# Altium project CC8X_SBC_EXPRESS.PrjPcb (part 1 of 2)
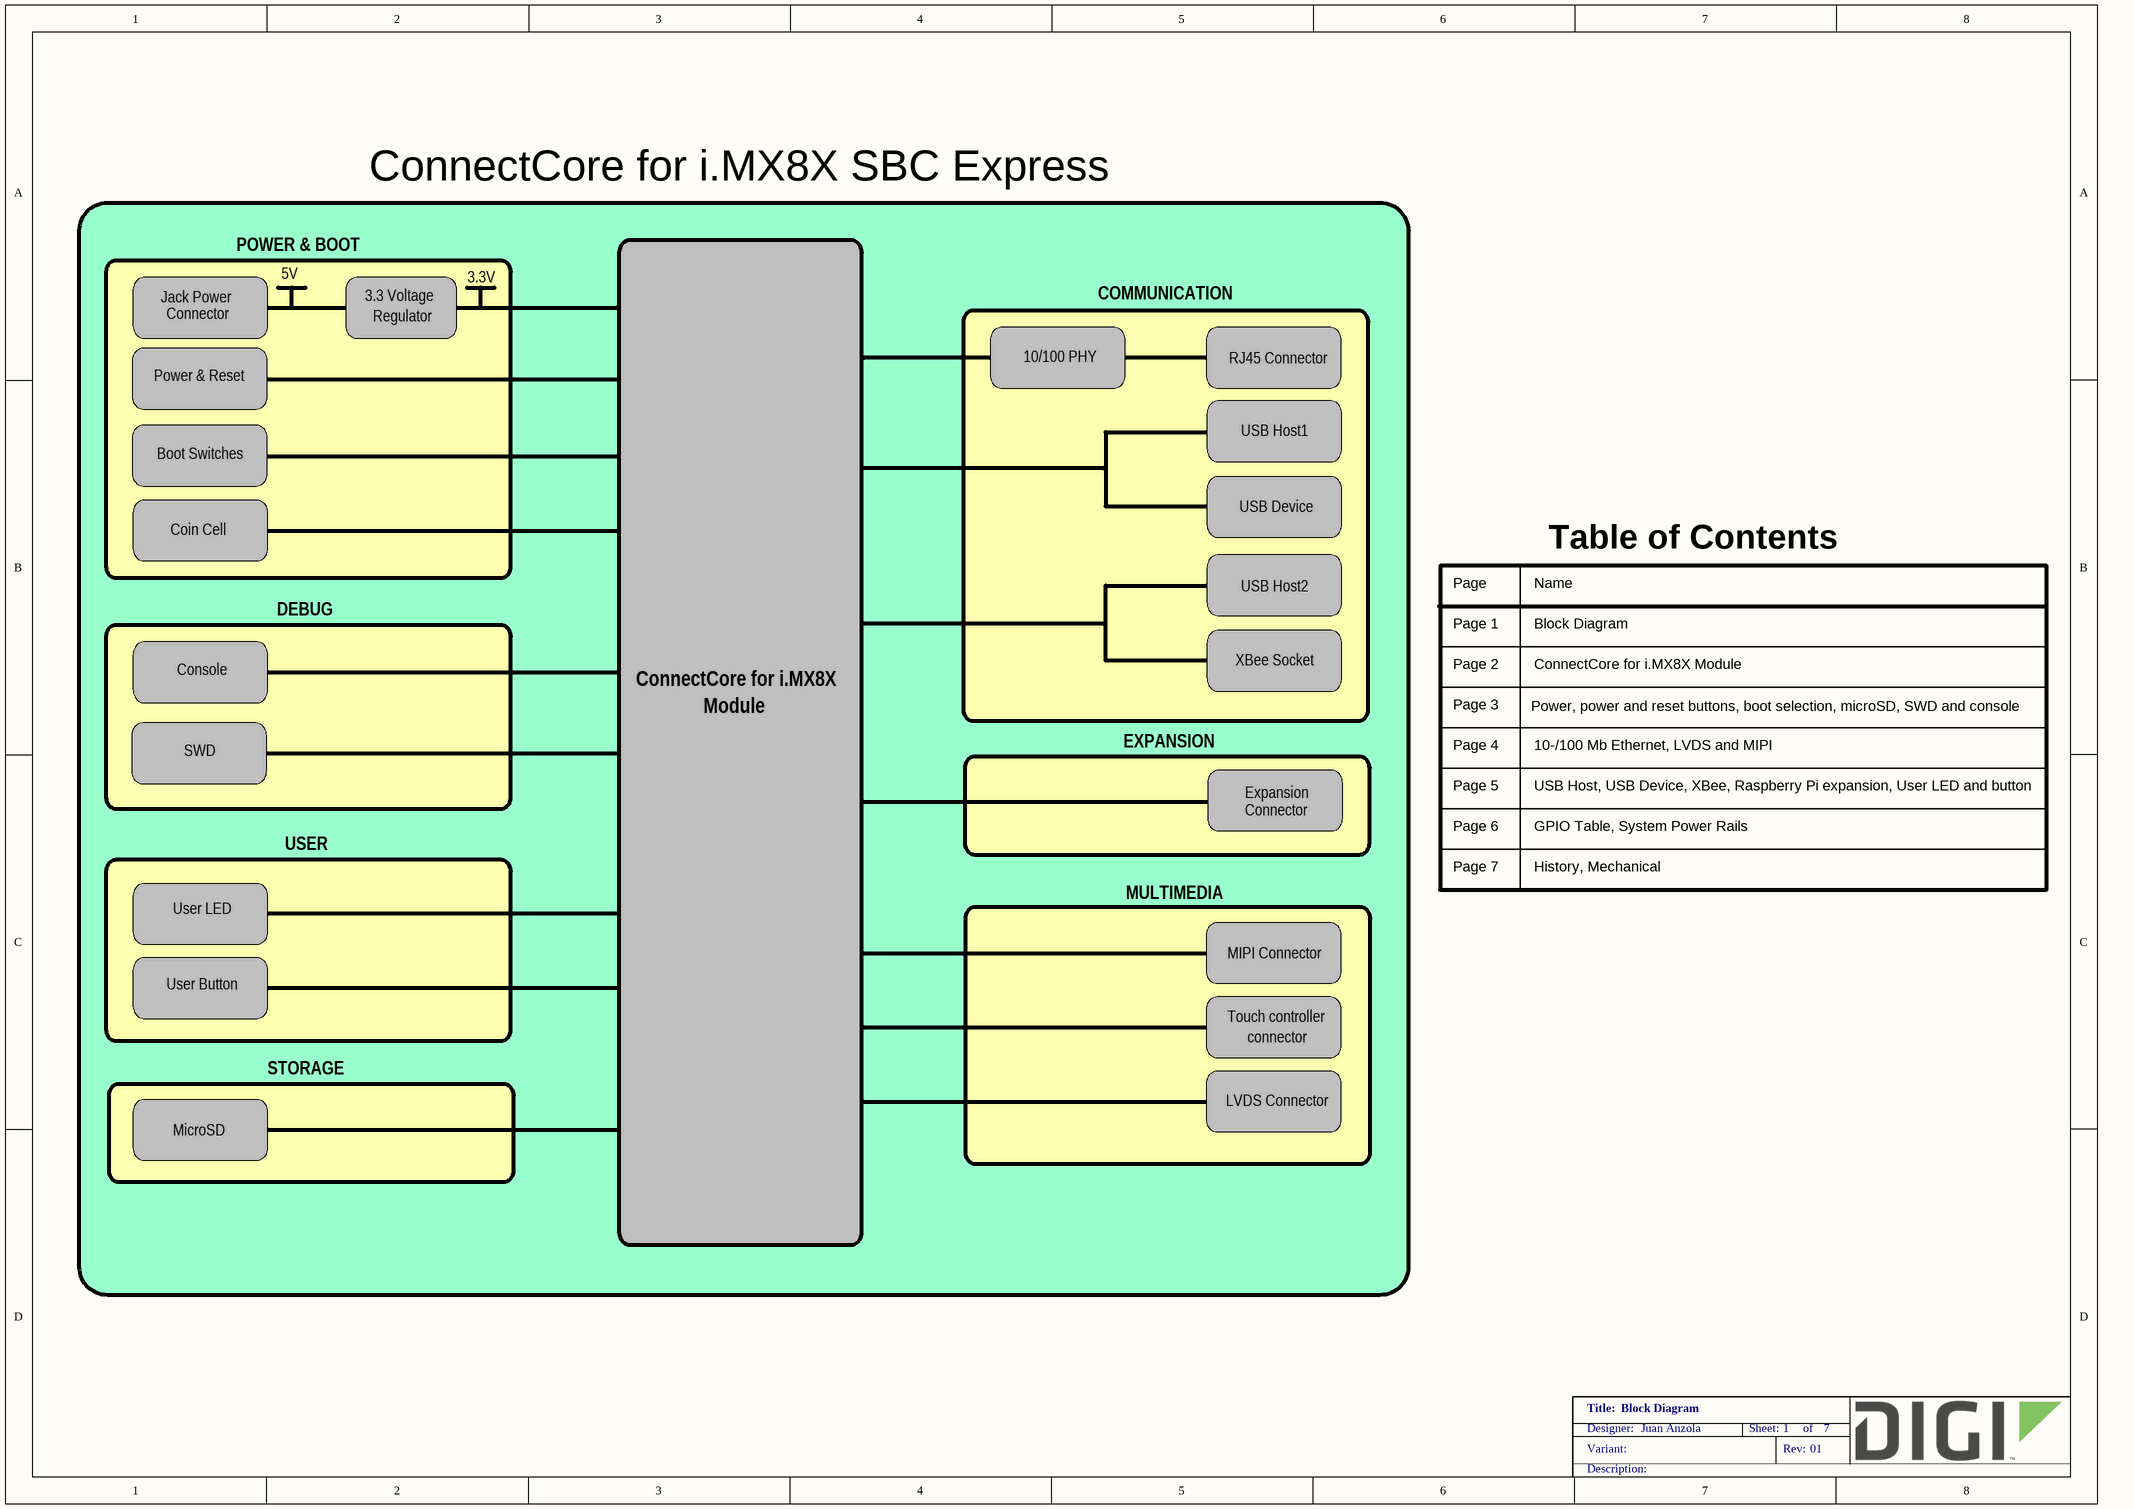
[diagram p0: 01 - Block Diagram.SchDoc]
VariantRevision: 01
7 sheets, 169 parts. Net scope: flat (ports and power ports of the same name join across sheets).
Board file: 30015582_02_A_CC8X_SBC_EXPRESS.PcbDoc
Sheets:
  01 - Block Diagram.SchDoc
  02 - CC8X Module.SchDoc
  03 - Power, boot mode, reset, console, microSD, SWD, Coin Cell.SchDoc
  04 - 10-100 Mb Ethernet, LVDS, MIPI.SchDoc
  05 - USB Host-Device, Raspberry PI expansion, User LED and button, XBee.SchDoc
  06 - GPIO Table, System Power rails.SchDoc
  07 - History, Mechanicals.SchDoc

## Sheet 01 - Block Diagram.SchDoc: Block Diagram
size A3; PageSetup: Record=PageOptions¦CenterHorizontal=True¦CenterVertical=True¦PrintScale=0.70¦XCorrection=1.00¦YCorrection=1.00¦PrintKind=0¦BorderSize=5000000¦LeftOffset=0¦BottomOffset=0¦Orientation=2¦PaperLength=4200¦PaperWidth=2970¦Scale=100¦PaperSource=7¦PrintQuality=600¦MediaType=1¦DitherType=10¦PaperKind=A4¦PrintScaleMode=1; Author: Juan Anzola; SheetNumber: 1; SheetTotal: 7

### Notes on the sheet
- ConnectCore for i.MX8X SBC Express
- Jack Power
- POWER & BOOT
- 5V
- 3.3 Voltage
- 3.3V
- COMMUNICATION
- Power & Reset
- Connector
- Regulator
- 10/100 PHY
- RJ45 Connector
- USB Host1
- Boot Switches
- USB Device
- Coin Cell
- Page
- Name
- Table of Contents
- DEBUG
- USB Host2
- Page 1
- Block Diagram
- Console
- ConnectCore for i.MX8X
- Module
- XBee Socket
- Page 2
- Page 3
- Power, power and reset buttons, boot selection, microSD, SWD and console
- ConnectCore for i.MX8X Module
- SWD
- EXPANSION
- Page 4
- 10-/100 Mb Ethernet, LVDS and MIPI
- USER
- Expansion
- Page 5
- Page 6
- USB Host, USB Device, XBee, Raspberry Pi expansion, User LED and button
- GPIO Table, System Power Rails
- User LED
- MULTIMEDIA
- Page 7
- History, Mechanical
- User Button
- MIPI Connector
- Touch controller
- connector
- STORAGE
- LVDS Connector
- MicroSD

## Sheet 02 - CC8X Module.SchDoc: ConnectCore for i.MX6UL module
size A2; PageSetup: Record=PageOptions¦CenterHorizontal=True¦CenterVertical=True¦PrintScale=0.71¦XCorrection=1.00¦YCorrection=1.00¦PrintKind=0¦BorderSize=5000000¦LeftOffset=0¦BottomOffset=0¦Orientation=2¦PaperLength=4200¦PaperWidth=2970¦Scale=100¦PaperSource=257¦PrintQuality=600¦MediaType=1¦DitherType=10¦PaperKind=A3¦PrintScaleMode=1; Author: Juan Anzola; Organization: Altium Limited; Address1: L3, 12a Rodborough Rd; Address2: Frenchs Forest; Address3: NSW; Address4: Australia 2086; SheetNumber: 2; SheetTotal: 7
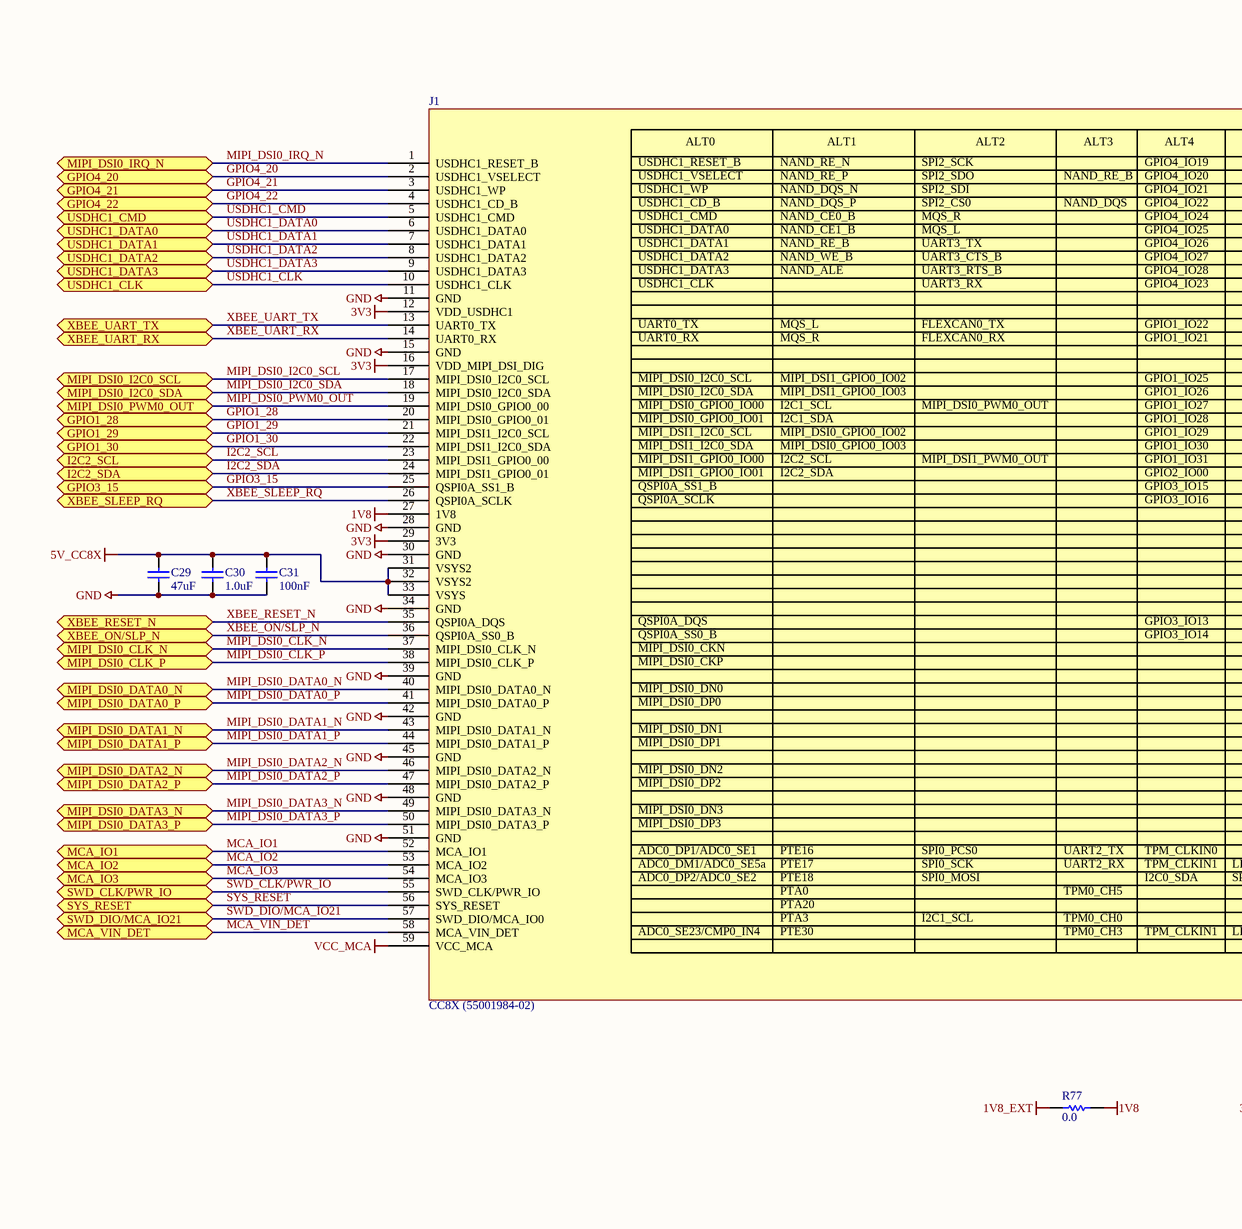
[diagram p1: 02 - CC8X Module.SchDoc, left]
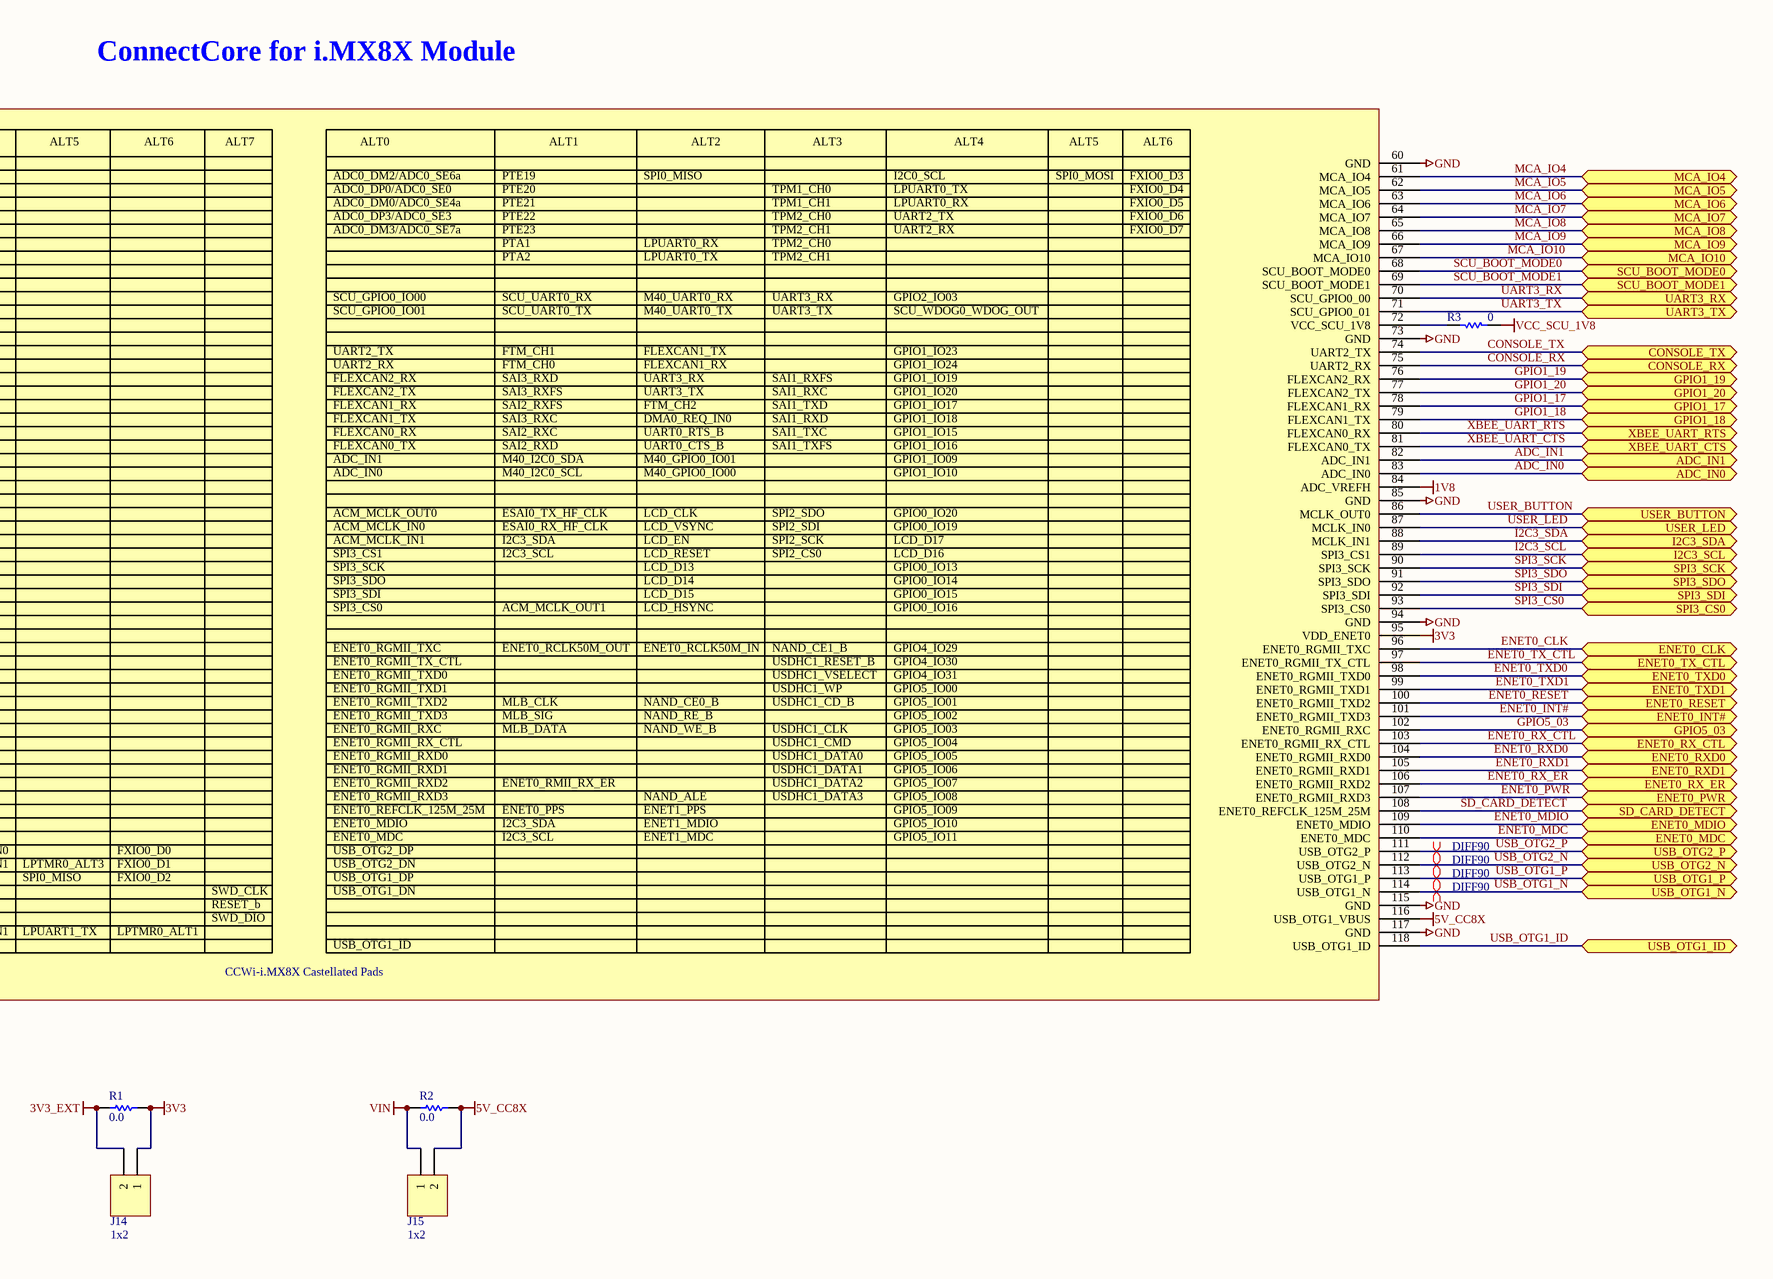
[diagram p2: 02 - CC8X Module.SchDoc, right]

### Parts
C29  47uF  [CAPC2013X145N]
C30  1.0uF  [CAPC1005X55L]
C31  100nF  [CAPC1005X55N]
J1  CC8X (55001984-02)  [CC8X_CASTELLATED]
J14  1x2  [FCI_68002-102HLF]
J15  1x2  [FCI_68002-102HLF]
R1  0.0  [RESC2013X70N]
R2  0.0  [RESC2013X70N]
R3  0  [RESC1005X40N]
R77  0.0  [RESC2013X70N]

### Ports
ADC_IN0 (bidir), ADC_IN1 (bidir), CONSOLE_RX (bidir), CONSOLE_TX (bidir), ENET0_CLK (bidir), ENET0_INT# (bidir), ENET0_MDC (bidir), ENET0_MDIO (bidir), ENET0_PWR (bidir), ENET0_RESET (bidir), ENET0_RX_CTL (bidir), ENET0_RX_ER (bidir), ENET0_RXD0 (bidir), ENET0_RXD1 (bidir), ENET0_TX_CTL (bidir), ENET0_TXD0 (bidir), ENET0_TXD1 (bidir), GPIO1_17 (bidir), GPIO1_18 (bidir), GPIO1_19 (bidir), GPIO1_20 (bidir), GPIO1_28 (bidir), GPIO1_29 (bidir), GPIO1_30 (bidir), GPIO3_15 (bidir), GPIO4_20 (bidir), GPIO4_21 (bidir), GPIO4_22 (bidir), GPIO5_03 (bidir), I2C2_SCL (bidir), I2C2_SDA (bidir), I2C3_SCL (bidir), I2C3_SDA (bidir), MCA_IO1 (bidir), MCA_IO2 (bidir), MCA_IO3 (bidir), MCA_IO4 (bidir), MCA_IO5 (bidir), MCA_IO6 (bidir), MCA_IO7 (bidir), MCA_IO8 (bidir), MCA_IO9 (bidir), MCA_IO10 (bidir), MCA_VIN_DET (bidir), MIPI_DSI0_CLK_N (bidir), MIPI_DSI0_CLK_P (bidir), MIPI_DSI0_DATA0_N (bidir), MIPI_DSI0_DATA0_P (bidir), MIPI_DSI0_DATA1_N (bidir), MIPI_DSI0_DATA1_P (bidir), MIPI_DSI0_DATA2_N (bidir), MIPI_DSI0_DATA2_P (bidir), MIPI_DSI0_DATA3_N (bidir), MIPI_DSI0_DATA3_P (bidir), MIPI_DSI0_I2C0_SCL (bidir), MIPI_DSI0_I2C0_SDA (bidir), MIPI_DSI0_IRQ_N (bidir), MIPI_DSI0_PWM0_OUT (bidir), SCU_BOOT_MODE0 (bidir), SCU_BOOT_MODE1 (bidir), SD_CARD_DETECT (bidir), SPI3_CS0 (bidir), SPI3_SCK (bidir), SPI3_SDI (bidir), SPI3_SDO (bidir), SWD_CLK/PWR_IO (bidir), SWD_DIO/MCA_IO21 (bidir), SYS_RESET (bidir), UART3_RX (bidir), UART3_TX (bidir), USB_OTG1_ID (bidir), USB_OTG1_N (bidir), USB_OTG1_P (bidir), USB_OTG2_N (bidir), USB_OTG2_P (bidir), USDHC1_CLK (bidir), USDHC1_CMD (bidir), USDHC1_DATA0 (bidir), USDHC1_DATA1 (bidir), USDHC1_DATA2 (bidir), USDHC1_DATA3 (bidir), USER_BUTTON (bidir), USER_LED (bidir), XBEE_ON/SLP_N (bidir), XBEE_RESET_N (bidir), XBEE_SLEEP_RQ (bidir), XBEE_UART_CTS (bidir), XBEE_UART_RTS (bidir), XBEE_UART_RX (bidir), XBEE_UART_TX (bidir)

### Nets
1V8: J1.27(1V8) J1.84(ADC_VREFH) R77.2
1V8_EXT: R77.1
3V3: J1.12(VDD_USDHC1) J1.16(VDD_MIPI_DSI_DIG) J1.29(3V3) J1.95(VDD_ENET0) J14.1 R1.2
3V3_EXT: J14.2 R1.1
5V_CC8X: C29.2 C30.2 C31.1 J1.31(VSYS2) J1.32(VSYS2) J1.33(VSYS) J1.116(USB_OTG1_VBUS) J15.2 R2.2
GND: C29.1 C30.1 C31.2 J1.11(GND) J1.15(GND) J1.28(GND) J1.30(GND) J1.34(GND) J1.39(GND) J1.42(GND) J1.45(GND) J1.48(GND) J1.51(GND) J1.60(GND) J1.73(GND) J1.85(GND) J1.94(GND) J1.115(GND) J1.117(GND)
VCC_MCA: J1.59(VCC_MCA)
VCC_SCU_1V8: R3.2
VIN: J15.1 R2.1
ADC_IN0: J1.83(ADC_IN0) ; port ADC_IN0
ADC_IN1: J1.82(ADC_IN1) ; port ADC_IN1
CONSOLE_RX: J1.75(UART2_RX) ; port CONSOLE_RX
CONSOLE_TX: J1.74(UART2_TX) ; port CONSOLE_TX
ENET0_CLK: J1.96(ENET0_RGMII_TXC) ; port ENET0_CLK
ENET0_INT#: J1.101(ENET0_RGMII_TXD3) ; port ENET0_INT#
ENET0_MDC: J1.110(ENET0_MDC) ; port ENET0_MDC
ENET0_MDIO: J1.109(ENET0_MDIO) ; port ENET0_MDIO
ENET0_PWR: J1.107(ENET0_RGMII_RXD3) ; port ENET0_PWR
ENET0_RESET: J1.100(ENET0_RGMII_TXD2) ; port ENET0_RESET
ENET0_RX_CTL: J1.103(ENET0_RGMII_RX_CTL) ; port ENET0_RX_CTL
ENET0_RX_ER: J1.106(ENET0_RGMII_RXD2) ; port ENET0_RX_ER
ENET0_RXD0: J1.104(ENET0_RGMII_RXD0) ; port ENET0_RXD0
ENET0_RXD1: J1.105(ENET0_RGMII_RXD1) ; port ENET0_RXD1
ENET0_TX_CTL: J1.97(ENET0_RGMII_TX_CTL) ; port ENET0_TX_CTL
ENET0_TXD0: J1.98(ENET0_RGMII_TXD0) ; port ENET0_TXD0
ENET0_TXD1: J1.99(ENET0_RGMII_TXD1) ; port ENET0_TXD1
GPIO1_17: J1.78(FLEXCAN1_RX) ; port GPIO1_17
GPIO1_18: J1.79(FLEXCAN1_TX) ; port GPIO1_18
GPIO1_19: J1.76(FLEXCAN2_RX) ; port GPIO1_19
GPIO1_20: J1.77(FLEXCAN2_TX) ; port GPIO1_20
GPIO1_28: J1.20(MIPI_DSI0_GPIO0_01) ; port GPIO1_28
GPIO1_29: J1.21(MIPI_DSI1_I2C0_SCL) ; port GPIO1_29
GPIO1_30: J1.22(MIPI_DSI1_I2C0_SDA) ; port GPIO1_30
GPIO3_15: J1.25(QSPI0A_SS1_B) ; port GPIO3_15
GPIO4_20: J1.2(USDHC1_VSELECT) ; port GPIO4_20
GPIO4_21: J1.3(USDHC1_WP) ; port GPIO4_21
GPIO4_22: J1.4(USDHC1_CD_B) ; port GPIO4_22
GPIO5_03: J1.102(ENET0_RGMII_RXC) ; port GPIO5_03
I2C2_SCL: J1.23(MIPI_DSI1_GPIO0_00) ; port I2C2_SCL
I2C2_SDA: J1.24(MIPI_DSI1_GPIO0_01) ; port I2C2_SDA
I2C3_SCL: J1.89(SPI3_CS1) ; port I2C3_SCL
I2C3_SDA: J1.88(MCLK_IN1) ; port I2C3_SDA
MCA_IO1: J1.52(MCA_IO1) ; port MCA_IO1
MCA_IO2: J1.53(MCA_IO2) ; port MCA_IO2
MCA_IO3: J1.54(MCA_IO3) ; port MCA_IO3
MCA_IO4: J1.61(MCA_IO4) ; port MCA_IO4
MCA_IO5: J1.62(MCA_IO5) ; port MCA_IO5
MCA_IO6: J1.63(MCA_IO6) ; port MCA_IO6
MCA_IO7: J1.64(MCA_IO7) ; port MCA_IO7
MCA_IO8: J1.65(MCA_IO8) ; port MCA_IO8
MCA_IO9: J1.66(MCA_IO9) ; port MCA_IO9
MCA_IO10: J1.67(MCA_IO10) ; port MCA_IO10
MCA_VIN_DET: J1.58(MCA_VIN_DET) ; port MCA_VIN_DET
MIPI_DSI0_CLK_N: J1.37(MIPI_DSI0_CLK_N) ; port MIPI_DSI0_CLK_N
MIPI_DSI0_CLK_P: J1.38(MIPI_DSI0_CLK_P) ; port MIPI_DSI0_CLK_P
MIPI_DSI0_DATA0_N: J1.40(MIPI_DSI0_DATA0_N) ; port MIPI_DSI0_DATA0_N
MIPI_DSI0_DATA0_P: J1.41(MIPI_DSI0_DATA0_P) ; port MIPI_DSI0_DATA0_P
MIPI_DSI0_DATA1_N: J1.43(MIPI_DSI0_DATA1_N) ; port MIPI_DSI0_DATA1_N
MIPI_DSI0_DATA1_P: J1.44(MIPI_DSI0_DATA1_P) ; port MIPI_DSI0_DATA1_P
MIPI_DSI0_DATA2_N: J1.46(MIPI_DSI0_DATA2_N) ; port MIPI_DSI0_DATA2_N
MIPI_DSI0_DATA2_P: J1.47(MIPI_DSI0_DATA2_P) ; port MIPI_DSI0_DATA2_P
MIPI_DSI0_DATA3_N: J1.49(MIPI_DSI0_DATA3_N) ; port MIPI_DSI0_DATA3_N
MIPI_DSI0_DATA3_P: J1.50(MIPI_DSI0_DATA3_P) ; port MIPI_DSI0_DATA3_P
MIPI_DSI0_I2C0_SCL: J1.17(MIPI_DSI0_I2C0_SCL) ; port MIPI_DSI0_I2C0_SCL
MIPI_DSI0_I2C0_SDA: J1.18(MIPI_DSI0_I2C0_SDA) ; port MIPI_DSI0_I2C0_SDA
MIPI_DSI0_IRQ_N: J1.1(USDHC1_RESET_B) ; port MIPI_DSI0_IRQ_N
MIPI_DSI0_PWM0_OUT: J1.19(MIPI_DSI0_GPIO0_00) ; port MIPI_DSI0_PWM0_OUT
SCU_BOOT_MODE0: J1.68(SCU_BOOT_MODE0) ; port SCU_BOOT_MODE0
SCU_BOOT_MODE1: J1.69(SCU_BOOT_MODE1) ; port SCU_BOOT_MODE1
SD_CARD_DETECT: J1.108(ENET0_REFCLK_125M_25M) ; port SD_CARD_DETECT
SPI3_CS0: J1.93(SPI3_CS0) ; port SPI3_CS0
SPI3_SCK: J1.90(SPI3_SCK) ; port SPI3_SCK
SPI3_SDI: J1.92(SPI3_SDI) ; port SPI3_SDI
SPI3_SDO: J1.91(SPI3_SDO) ; port SPI3_SDO
SWD_CLK/PWR_IO: J1.55(SWD_CLK/PWR_IO) ; port SWD_CLK/PWR_IO
SWD_DIO/MCA_IO21: J1.57(SWD_DIO/MCA_IO0) ; port SWD_DIO/MCA_IO21
SYS_RESET: J1.56(SYS_RESET) ; port SYS_RESET
UART3_RX: J1.70(SCU_GPIO0_00) ; port UART3_RX
UART3_TX: J1.71(SCU_GPIO0_01) ; port UART3_TX
USB_OTG1_ID: J1.118(USB_OTG1_ID) ; port USB_OTG1_ID
USB_OTG1_N: J1.114(USB_OTG1_N) ; port USB_OTG1_N
USB_OTG1_P: J1.113(USB_OTG1_P) ; port USB_OTG1_P
USB_OTG2_N: J1.112(USB_OTG2_N) ; port USB_OTG2_N
USB_OTG2_P: J1.111(USB_OTG2_P) ; port USB_OTG2_P
USDHC1_CLK: J1.10(USDHC1_CLK) ; port USDHC1_CLK
USDHC1_CMD: J1.5(USDHC1_CMD) ; port USDHC1_CMD
USDHC1_DATA0: J1.6(USDHC1_DATA0) ; port USDHC1_DATA0
USDHC1_DATA1: J1.7(USDHC1_DATA1) ; port USDHC1_DATA1
USDHC1_DATA2: J1.8(USDHC1_DATA2) ; port USDHC1_DATA2
USDHC1_DATA3: J1.9(USDHC1_DATA3) ; port USDHC1_DATA3
USER_BUTTON: J1.86(MCLK_OUT0) ; port USER_BUTTON
USER_LED: J1.87(MCLK_IN0) ; port USER_LED
XBEE_ON/SLP_N: J1.36(QSPI0A_SS0_B) ; port XBEE_ON/SLP_N
XBEE_RESET_N: J1.35(QSPI0A_DQS) ; port XBEE_RESET_N
XBEE_SLEEP_RQ: J1.26(QSPI0A_SCLK) ; port XBEE_SLEEP_RQ
XBEE_UART_CTS: J1.81(FLEXCAN0_TX) ; port XBEE_UART_CTS
XBEE_UART_RTS: J1.80(FLEXCAN0_RX) ; port XBEE_UART_RTS
XBEE_UART_RX: J1.14(UART0_RX) ; port XBEE_UART_RX
XBEE_UART_TX: J1.13(UART0_TX) ; port XBEE_UART_TX
NetJ1_72: J1.72(VCC_SCU_1V8) R3.1

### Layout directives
differential pair; net class DIFF90: USB_OTG1_N, USB_OTG1_P, USB_OTG2_N, USB_OTG2_P

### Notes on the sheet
- ConnectCore for i.MX8X Module

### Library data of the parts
C29 = 1000501: CAP CER 47UF 6.3V 20% X5R 0805; Part_Type: Capacitor; Manufacturer: Taiyo Yuden; Manufacturer_Part_Number: JMK212BJ476MG-T; Digi_PN: 14050627; Component_Life_Cycle_State: Reviewed; Area: 6.4; Project: SDR Prototype RF Board
C30 = 1000073: CAP CER 1UF 6.3V 20% X5R 0402; Part_Type: Capacitor; Manufacturer: Murata; Manufacturer_Part_Number: GRM155R60J105ME19D; Digi_PN: 14050543; Component_Life_Cycle_State: Proven; Area: 0.95; Project: Adjustable Foundation
C31 = 1000006: CAP 100nF 16V 10% X7R 0402; Part_Type: Capacitor; Manufacturer: Murata; Manufacturer_Part_Number: GRM155R71C104KA88D; Component_Life_Cycle_State: CAD Reviewed; Area: 0.95; Project: KITT; Tolerance: 10; Digi_PN: 14050552
J1 = 1002609: CC8X castellated - 55001984-02; Part_Type: Module; Manufacturer: DIGI; Component_Life_Cycle_State: Pending; Area: 1800
J14 J15 = 1001128: CONN HEADER 2POS .100" SGL GOLD; Part_Type: Connector; Manufacturer: Samtec; Manufacturer_Part_Number: TSW-102-07-G-S; Digi_PN: 00120002; Component_Life_Cycle_State: Reviewed; Area: 12,9032; Project: CCWMX6_SBC board
R1 R2 R77 = 1001557: RES 0.0 OHM 1/8W JUMP 0805 SMD; Part_Type: Resistor; Manufacturer: Yageo; Manufacturer_Part_Number: RC0805JR-070RL; Note: 13051095 = Digi No. for GE WDNU; Digi_PN: TR00037; Component_Life_Cycle_State: Reviewed; Area: 5,8; Project: WDNU-II; Power_WV_SRF: 125
R3 = 1000076: RES 0.0 OHM 1/10W 0402 SMD; Part_Type: Resistor; Manufacturer: Panasonic - ECG; Manufacturer_Part_Number: ERJ-2GE0R00X; Digi_PN: 13050387; Component_Life_Cycle_State: Proven; Area: 0,95; Project: Adjustable Foundation; Power_WV_SRF: 10

## Sheet 03 - Power, boot mode, reset, console, microSD, SWD, Coin Cell.SchDoc: Power, Boot, Power and Reset buttons
size A3; PageSetup: Record=PageOptions¦CenterHorizontal=True¦CenterVertical=True¦PrintScale=0.70¦XCorrection=1.00¦YCorrection=1.00¦PrintKind=0¦BorderSize=5000000¦LeftOffset=0¦BottomOffset=0¦Orientation=2¦PaperLength=4200¦PaperWidth=2970¦Scale=100¦PaperSource=7¦PrintQuality=600¦MediaType=1¦DitherType=10¦PaperKind=A4¦PrintScaleMode=1; Author: Juan Anzola; SheetNumber: 3; SheetTotal: 7
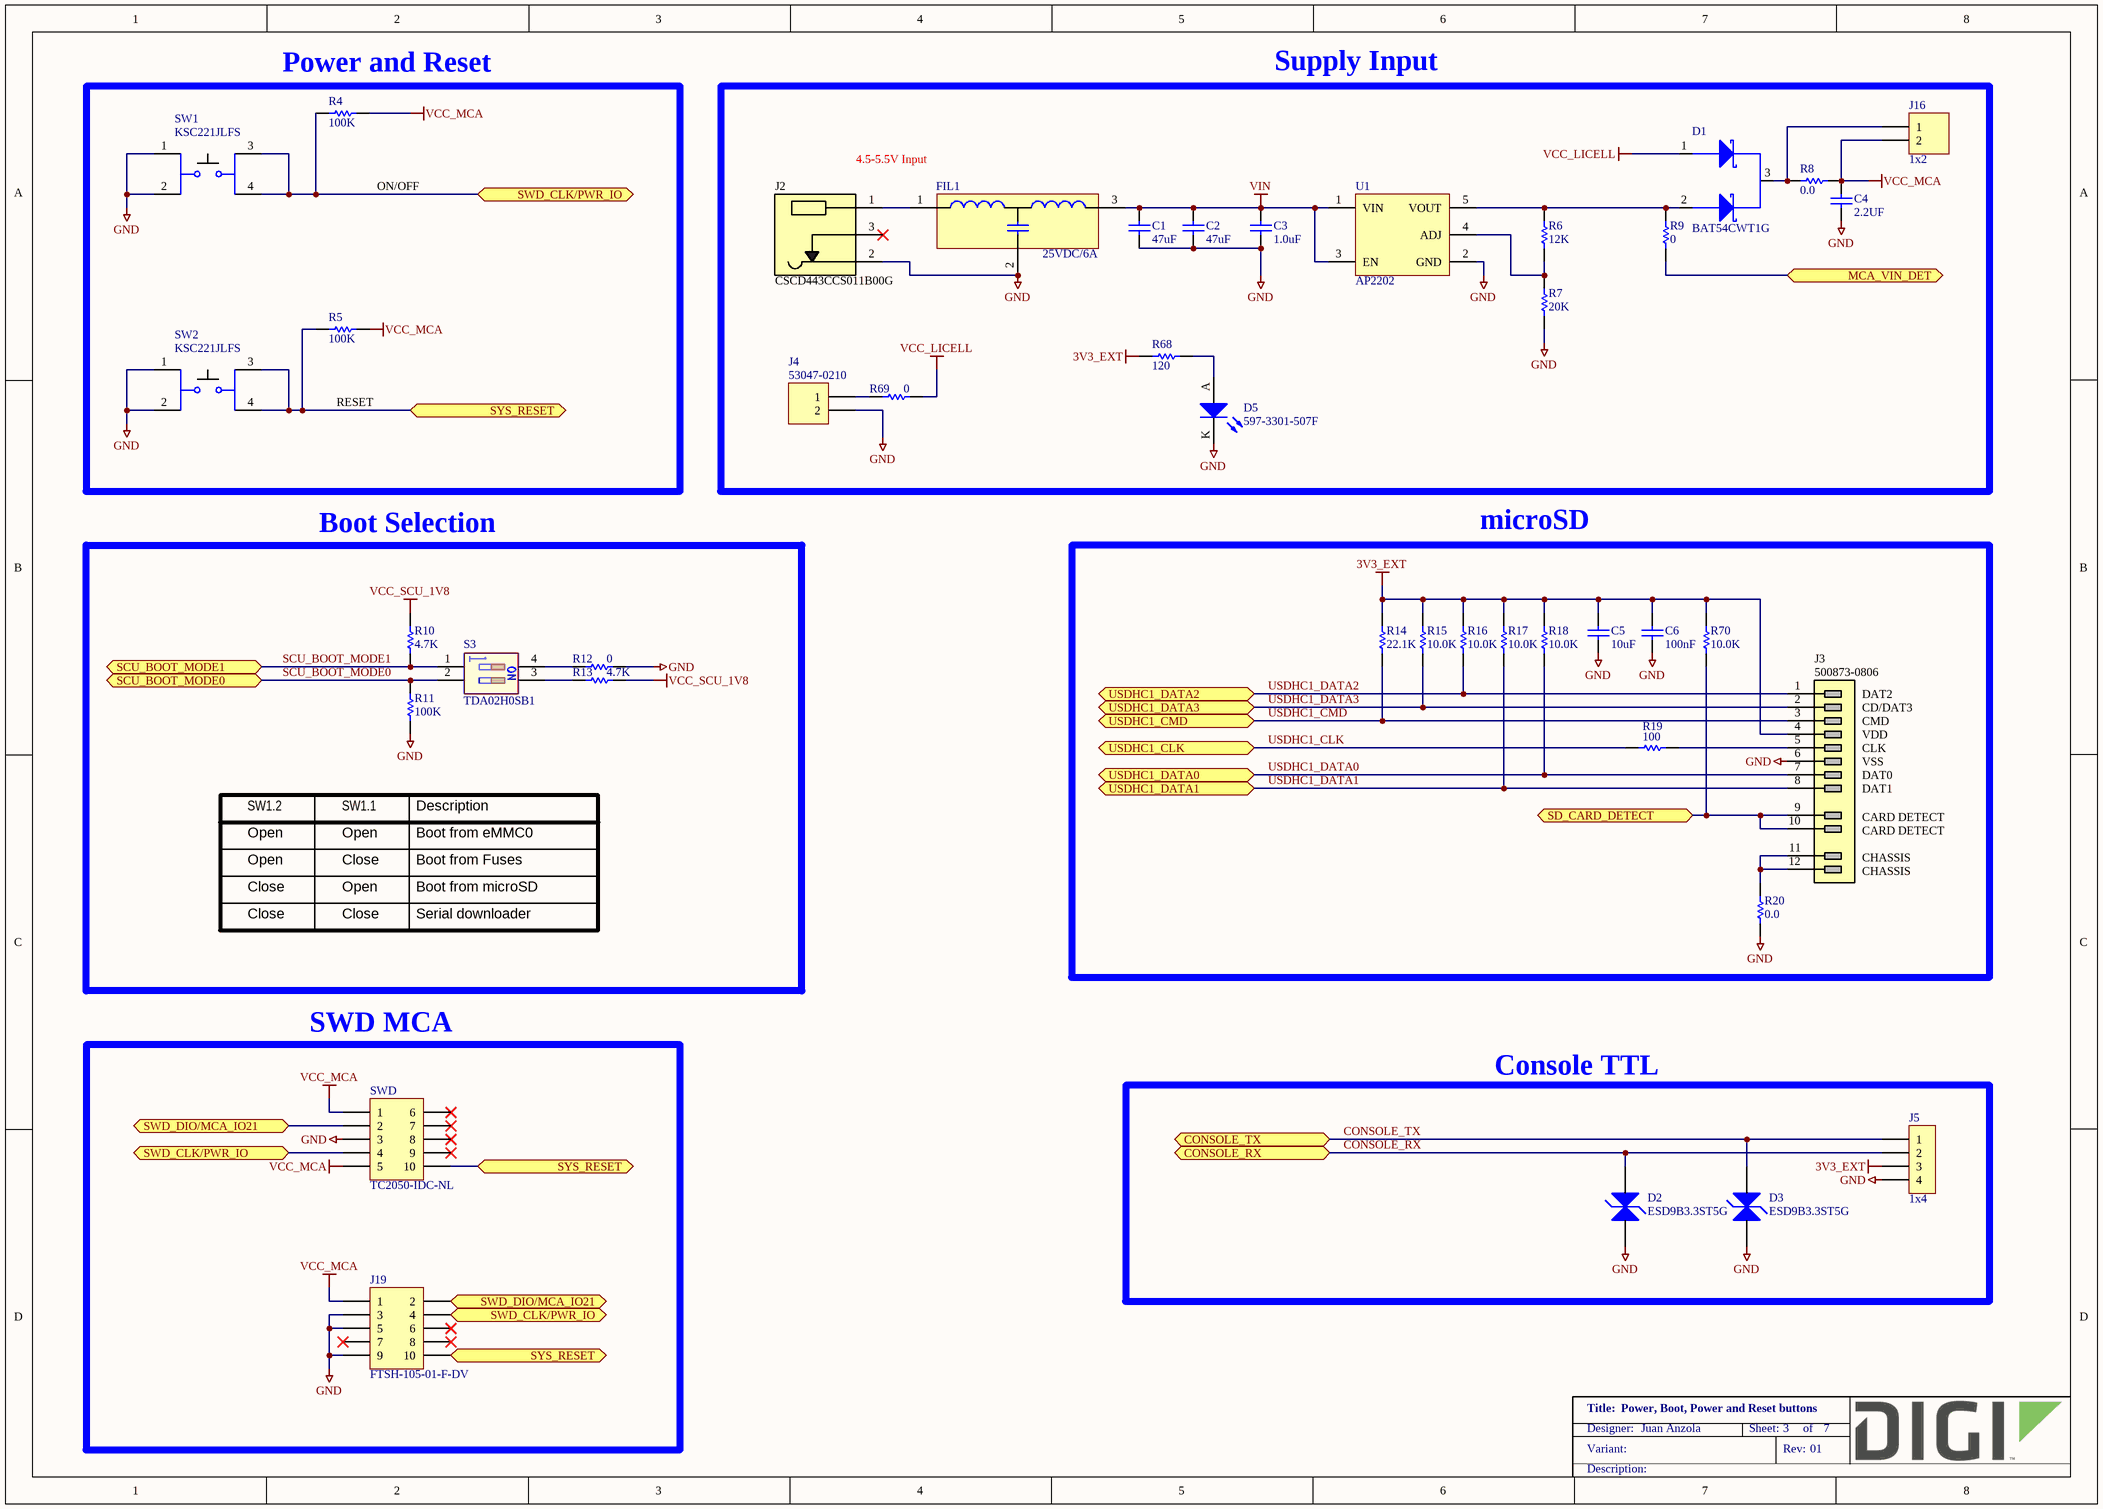
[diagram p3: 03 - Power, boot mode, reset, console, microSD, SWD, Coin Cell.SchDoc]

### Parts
C1  47uF  [CAPC2013X145N]
C2  47uF  [CAPC2013X145N]
C3  1.0uF  [CAPC1005X55L]
C4  2.2UF  [CAPC1608X90N]
C5  10uF  [CAPC1005X55N]
C6  100nF  [CAPC1005X55N]
D1  BAT54CWT1G  [SOT65P210X100-3AN]
D2  ESD9B3.3ST5G  [SODFL1006X43AN12]
D3  ESD9B3.3ST5G  [SODFL1006X43AN12]
D5  597-3301-507F  [LEDM3020X130N]
FIL1  25VDC/6A  [FIL_ELKEA]
J2  CSCD443CCS011B00G  [conn_CSCD443CCS011B00G]
J3  500873-0806  [MOLEX_500873-0806]
J4  Manufacturer_Part_Number: 53047-0210  [MOLEX_53047-0210]  (hidden comment: 1x2P)
J5  1x4  [MOLEX_53047-0410]
J16  1x2  [FCI_68002-102HLF]
J19  FTSH-105-01-F-DV  [SAMTEC_FTSH-105-01-F-DV]
R4  100K  [RESC1005X40N]
R5  100K  [RESC1005X40N]
R6  12K  [RESC1609X55N]
R7  20K  [RESC1609X55N]
R8  0.0  [RESC2013X70N]
R9  0  [RESC1005X40N]
R10  4.7K  [RESC1005X40N]
R11  100K  [RESC1005X40N]
R12  0  [RESC1005X40N]
R13  4.7K  [RESC1005X40N]
R14  22.1K  [RESC1005X40N]
R15  10.0K  [RESC1005X40N]
R16  10.0K  [RESC1005X40N]
R17  10.0K  [RESC1005X40N]
R18  10.0K  [RESC1005X40N]
R19  100  [RESC1005X40N]
R20  0.0  [RESC2013X70N]
R68  120  [RESC1005X40N]
R69  0  [RESC1005X40N]
R70  10.0K  [RESC1005X40N]
S3  TDA02H0SB1  [SW_TDA02]
SW1  KSC221JLFS  [SW_KSC221J]
SW2  KSC221JLFS  [SW_KSC221J]
SWD  TC2050-IDC-NL  [TC_TC2050-IDC-NL]  (no BOM)
U1  AP2202  [SOT95P280X145-5N]

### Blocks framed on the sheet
Power and Reset: R4 R5 SW1 SW2
Supply Input: C1-C4 D1 D5 FIL1 J2 J4 J16 R6-R9 R68 R69 U1
Boot Selection: R10-R13 S3
microSD: C5 C6 J3 R14-R20 R70
SWD MCA: J19 SWD
Console TTL: D2 D3 J5

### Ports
CONSOLE_RX (bidir), CONSOLE_TX (bidir), MCA_VIN_DET (bidir), SCU_BOOT_MODE0 (bidir), SCU_BOOT_MODE1 (bidir), SD_CARD_DETECT (bidir), SWD_CLK/PWR_IO (bidir), SWD_DIO/MCA_IO21 (bidir), SYS_RESET (bidir), USDHC1_CLK (bidir), USDHC1_CMD (bidir), USDHC1_DATA0 (bidir), USDHC1_DATA1 (bidir), USDHC1_DATA2 (bidir), USDHC1_DATA3 (bidir)

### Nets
3V3_EXT: C5.2 C6.2 J3.4 J5.3 R14.2 R15.2 R16.2 R17.2 R18.2 R68.1 R70.2
GND: C1.1 C2.1 C3.1 C4.1 C5.1 C6.1 D2.1 D3.1 D5.K FIL1.2 J2.2 J3.6 J4.2 J5.4 J19.3 J19.5 J19.9 R7.1 R11.1 R12.2 R20.1 SW1.1 SW1.2 SW2.1 SW2.2 SWD.3 U1.2(GND)
VCC_LICELL: D1.1 R69.2
VCC_MCA: C4.2 J16.2 J19.1 R4.1 R5.1 R8.2 SWD.1 SWD.5
VCC_SCU_1V8: R10.2 R13.2
VIN: C1.2 C2.2 C3.2 FIL1.3(GND) U1.1(VIN) U1.3(EN)
CONSOLE_RX: D2.2 J5.2 ; port CONSOLE_RX
CONSOLE_TX: D3.2 J5.1 ; port CONSOLE_TX
MCA_VIN_DET: R9.1 ; port MCA_VIN_DET
SCU_BOOT_MODE0: R11.2 S3.2(A2) ; port SCU_BOOT_MODE0
SCU_BOOT_MODE1: R10.1 S3.1(A1) ; port SCU_BOOT_MODE1
SD_CARD_DETECT: J3.9 J3.10 R70.1 ; port SD_CARD_DETECT
SWD_CLK/PWR_IO: J19.4 R4.2 SW1.3 SW1.4 SWD.4 ; port SWD_CLK/PWR_IO
SWD_DIO/MCA_IO21: J19.2 SWD.2 ; port SWD_DIO/MCA_IO21
SYS_RESET: J19.10 R5.2 SW2.3 SW2.4 SWD.10 ; port SYS_RESET
USDHC1_CLK: R19.1 ; port USDHC1_CLK
USDHC1_CMD: J3.3 R14.1 ; port USDHC1_CMD
USDHC1_DATA0: J3.7 R18.1 ; port USDHC1_DATA0
USDHC1_DATA1: J3.8 R17.1 ; port USDHC1_DATA1
USDHC1_DATA2: J3.1 R16.1 ; port USDHC1_DATA2
USDHC1_DATA3: J3.2 R15.1 ; port USDHC1_DATA3
NetD1_2: D1.2 R6.2 R9.2 U1.5(VOUT)
NetD1_3: D1.3 J16.1 R8.1
NetD5_A: D5.A R68.2
NetFIL1_1: FIL1.1(GND) J2.1
NetJ3_5: J3.5 R19.2
NetJ3_11: J3.11 J3.12 R20.2
NetJ4_1: J4.1 R69.1
NetR6_1: R6.1 R7.2 U1.4(ADJ)
NetR12_1: R12.1 S3.4(B1)
NetR13_1: R13.1 S3.3(B2)

Not connected (* = marked no-connect by the designer): J2 3*; J19 6* 7* 8*; SWD 6* 7* 8* 9*

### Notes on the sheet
- 4.5-5.5V Input
- ON/OFF
- RESET
- Open
- SW1.2
- SW1.1
- Description
- Boot from eMMC0
- Close
- Boot from Fuses
- Boot from microSD
- Serial downloader

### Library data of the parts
C1 C2 = 1000501: as C29 on sheet 02 - CC8X Module
C3 = 1000073: as C30 on sheet 02 - CC8X Module
C4 = 1001303: CAP CER 2.2UF 16V 10% X5R 0603; Part_Type: Capacitor; Manufacturer: TDK Corporation; Manufacturer_Part_Number: C1608X5R1C225K080AB; Digi_PN: 14050730; Component_Life_Cycle_State: Reviewed; Area: 2,27; Project: Pinnacle
C5 = 1001168: CAP CER 10UF 10V 20% X5R 0402; Part_Type: Capacitor; Manufacturer: Samsung; Manufacturer_Part_Number: CL05A106MP5NUNC; Digi_PN: 14050689; Component_Life_Cycle_State: Reviewed; Area: 0.95; Project: CCWMX6_SBC board
C6 = 1000006: as C31 on sheet 02 - CC8X Module
D1 = 1000794: DIODE SCHOTTKY 30V 200MA SOT323; Part Number: SDS1920004; Manufacturer: Fairchild Semiconductor; Manufacturer Alt 1: none; Manufacturer Part Num: 0082610201; Part_Type: Diodes; Digi_PN: 17050561; Component_Life_Cycle_State: CAD Reviewed; Area: 7,68; Project: SmartMeter2
D2 D3 = 1001637: TVS DIODE 3.3VWM SOD923; Part_Type: Diodes; Manufacturer: On Semiconductor; Digi_PN: 17050883; Component_Life_Cycle_State: Reviewed; Area: 1,01; Project: CareTaker IV
D5 = 1001189: LED GREEN 573NM 1208 SMD; Manufacturer: Dialight; Note: 17050846 = Digi PN for GE WDNU II; Digi_PN: 17050183; Component_Life_Cycle_State: Reviewed; Area: 6; Project: CCWMX6_SBC board
FIL1 = 1001918: DNF 2 MHZ -1000 MHZ SMD; Part_Type: Filter; Manufacturer: Panasonic - ECG; Manufacturer_Part_Number: ELKEA333FA; Digi_PN: 21000532; Component_Life_Cycle_State: Reviewed; Area: 22; Project: CCWMX6_SBC board
J2 = 1001105: DC Power Jack; Part_Type: Connector; Manufacturer: Bobbintron Electrical Corp; Digi_PN: 18000302; Component_Life_Cycle_State: Reviewed; Area: 137; Project: CCWMX6_SBC board
J3 = 1001118: CONN TRANSFLSH R/A PUSH-PUSH SMD; Part_Type: Connector; Manufacturer: Molex; Digi_PN: MB03015; Component_Life_Cycle_State: Reviewed; Area: 213; Project: CCWMX6_SBC board
J4 = 1001136: CONN HEADER 2POS 1.25MM VERT TIN; Part_Type: Connector; Manufacturer: Molex; Component_Life_Cycle_State: Reviewed; Area: 13.6; Project: CCWMX6_SBC board; Digi_PN: 18050343
J5 = 1001137: CONN HEADER 4POS 1.25MM VERT TIN; Part_Type: Connector; Manufacturer: Molex; Manufacturer_Part_Number: 53047-0410; Digi_PN: 18050344; Component_Life_Cycle_State: Reviewed; Area: 21,6; Project: CCWMX6_SBC board
J16 = 1001128: as J14 on sheet 02 - CC8X Module
J19 = 1000034: CONN HEADER 10POS DUAL .05" SMD; Part_Type: Connector; Manufacturer: Samtec; Note: 18000715 = Digi No. for GE WDNU; Digi_PN: 18000539; Component_Life_Cycle_State: Proven; Area: 43,55; Project: Adjustable Foundation
R4 R5 R15-R18 R70 = 1000537: RES 10.0K OHM 1/10W 1% 0402 SMD; Part_Type: Resistor; Manufacturer: Panasonic - ECG; Manufacturer_Part_Number: ERJ-2RKF1002X; Component_Life_Cycle_State: CAD Reviewed; Area: 0.95; Project: KITT; Power_WV_SRF: 100; Digi_PN: 13051084
R6 = 1001200: RES 12.0K OHM 1/10W 1% 0603 SMD; Part_Type: Resistor; Manufacturer: Yageo; Manufacturer_Part_Number: RC0603FR-0712KL; Digi_PN: 13050531; Component_Life_Cycle_State: Reviewed; Area: 2,5; Project: LuCoV2; Power_WV_SRF: 100; Tolerance: 1
R7 = 1000142: RES 20K OHM 1/10W 5% 0603 SMD; Part_Type: Resistor; Manufacturer: Panasonic - ECG; Manufacturer_Part_Number: ERJ-3GEYJ203V; Digi_PN: 13050013; Component_Life_Cycle_State: Reviewed; Area: 2,5; Project: Adjustable Foundation; Power_WV_SRF: 100; Tolerance: 5
R8 = 1001557: as R1 on sheet 02 - CC8X Module
R9 = 1000076: RES 0.0 OHM 1/10W 0402 SMD; Part_Type: Resistor; Manufacturer: Panasonic - ECG; Manufacturer_Part_Number: ERJ-2GE0R00X; Component_Life_Cycle_State: Proven; Area: 0.95; Project: Adjustable Foundation; Power_WV_SRF: 10; Digi_PN: 13050387
R10 R13 = 1000038: RES 4.7K OHM 1/10W 5% 0402 SMD; Part_Type: Resistor; Manufacturer: Panasonic - ECG; Manufacturer_Part_Number: ERJ-2GEJ472X; Digi_PN: 13050549; Component_Life_Cycle_State: Proven; Area: 0,95; Project: Adjustable Foundation; Power_WV_SRF: 100; Tolerance: 5
R11 = 1000480: RES 100K OHM 1/10W 1% 0402 SMD; Part_Type: Resistor; Manufacturer: Panasonic - ECG; Manufacturer_Part_Number: ERJ-2RKF1003X; Digi_PN: 13051063; Component_Life_Cycle_State: CAD Reviewed; Area: 0,95; Project: KITT; Power_WV_SRF: 100
R12 R69 = 1000076: as R3 on sheet 02 - CC8X Module
R14 = 1001149: RES 22.1K OHM 1/16W 1% 0402 SMD; Part_Type: Resistor; Manufacturer: Vishay Dale; Manufacturer_Part_Number: CRCW040222K1FKED; Digi_PN: 13050450; Component_Life_Cycle_State: Reviewed; Area: 0.95; Project: CCWMX6_SBC board; Power_WV_SRF: 0.063; Tolerance: ±100ppm/°C
R19 = 1000467: RES 100 OHM 1/10W 1% 0402 SMD; Part_Type: Resistor; Manufacturer: Panasonic - ECG; Manufacturer_Part_Number: ERJ-2RKF1000X; Component_Life_Cycle_State: CAD Reviewed; Area: 0.95; Project: KITT; Digi_PN: 13051087
R20 = 1001557: RES 0.0 OHM 1/8W JUMP 0805 SMD; Part_Type: Resistor; Manufacturer: Yageo; Manufacturer_Part_Number: RC0805JR-070RL; Note: 13051095 = Digi No. for GE WDNU; Digi_PN: TR00037; Component_Life_Cycle_State: Reviewed; Area: 5.8; Project: WDNU-II; Power_WV_SRF: 125
R68 = 1001158: RES 120 OHM 1/16W 1% 0402 SMD; Part_Type: Resistor; Manufacturer: Yageo; Manufacturer_Part_Number: RC0402FR-07120RL; Digi_PN: 13050832; Component_Life_Cycle_State: Reviewed; Area: 0.95; Project: CCWMX6_SBC board; Note: 13051102 = Digi No. for GE WDNU
S3 = 1001500: SWITCH DIP 2POS HALF PITCH 24V; Manufacturer: C&K Components; Note: 22000296 = Digi No. for GE WDNU; Digi_PN: 22000060; Component_Life_Cycle_State: Reviewed; Area: 34,3; Project: CCWMX6_SBC board
SW1 SW2 = 1001124: SWITCH TACTILE SPST-NO 0.05A 32V; Manufacturer: ITT; Digi_PN: 22000059; Component_Life_Cycle_State: Reviewed; Area: 37; Project: CCWMX6_SBC board; Note: 22000295 = Digi No. for GE WDNU
SWD = CAD0066: CBL PLUG-OF-NAILS 10-PIN; Part_Type: Test Point; Component_Life_Cycle_State: Created; Area: 8; Project: CCWMX6_SBC board
U1 = 1001979: IC REG LDO ADJ 0.15A SOT25; Part_Type: Regulator; Manufacturer: Diodes, Inc.; Manufacturer_Part_Number: AP2202K-ADJTRG1; Digi_PN: 17050874; Component_Life_Cycle_State: Created; Area: 8,9; Project: iMX6UL+PMIC

## Sheet 04 - 10-100 Mb Ethernet, LVDS, MIPI.SchDoc: 10/100M Ethernet, Antenna
size A3; PageSetup: Record=PageOptions¦CenterHorizontal=True¦CenterVertical=True¦PrintScale=0.70¦XCorrection=1.00¦YCorrection=1.00¦PrintKind=0¦BorderSize=5000000¦LeftOffset=0¦BottomOffset=0¦Orientation=2¦PaperLength=4200¦PaperWidth=2970¦Scale=100¦PaperSource=7¦PrintQuality=600¦MediaType=1¦DitherType=10¦PaperKind=A4¦PrintScaleMode=1; Author: Juan Anzola; SheetNumber: 4; SheetTotal: 7
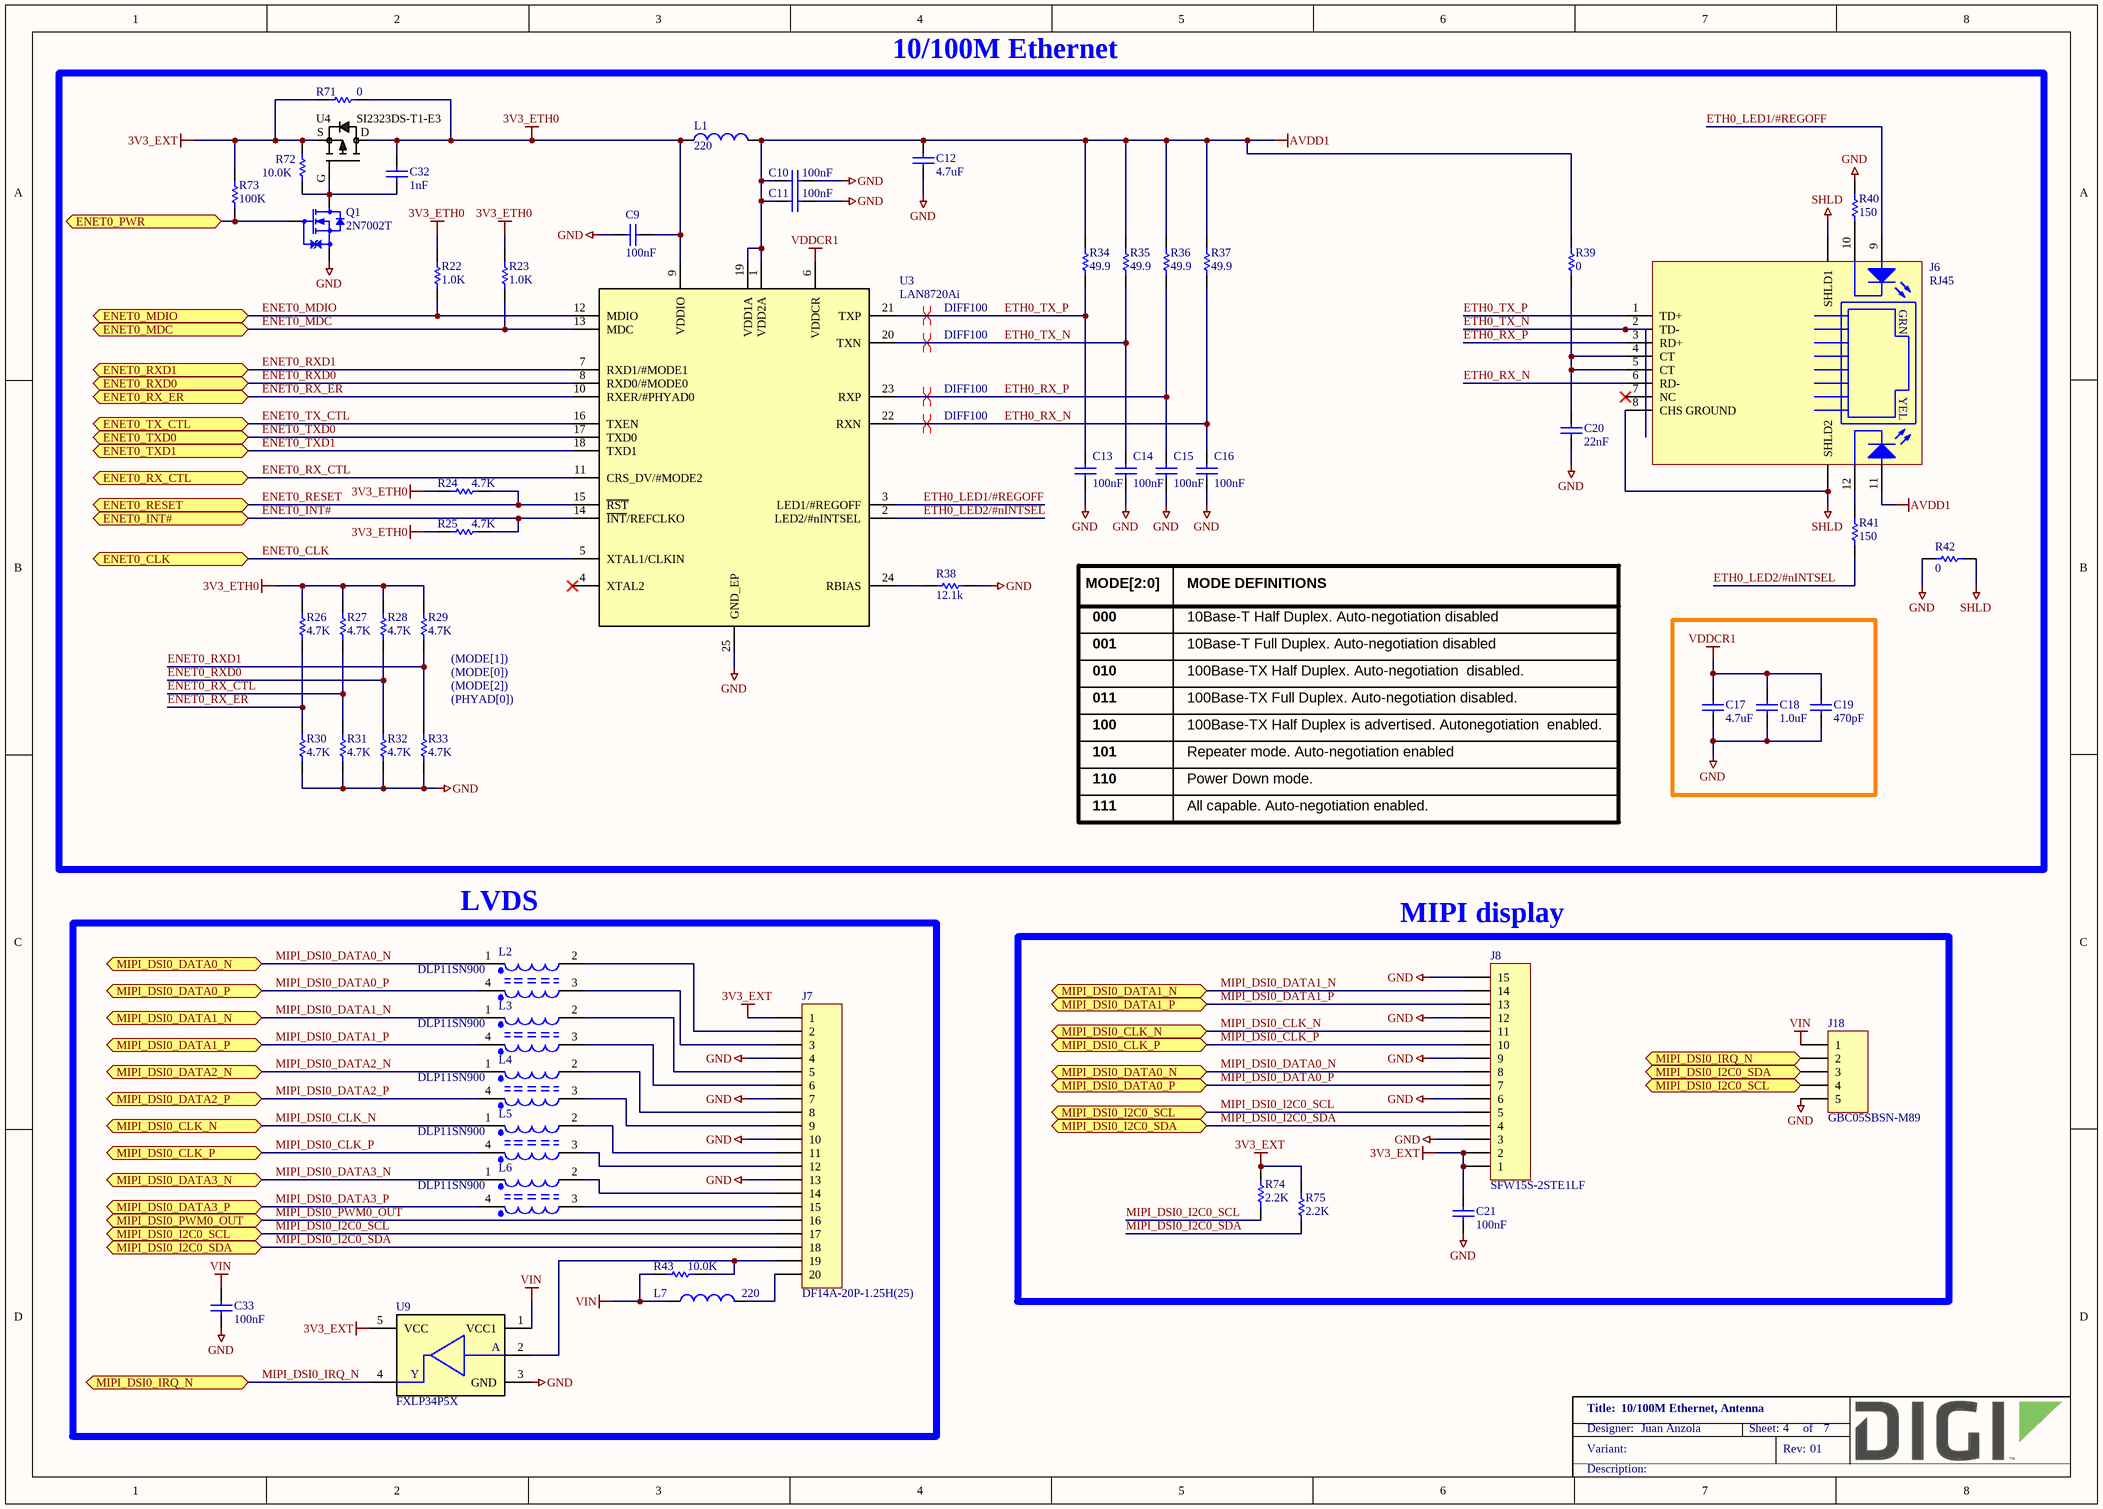
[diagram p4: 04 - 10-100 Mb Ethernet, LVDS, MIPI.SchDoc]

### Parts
C9  100nF  [CAPC1005X55N]
C10  100nF  [CAPC1005X55N]
C11  100nF  [CAPC1005X55N]
C12  4.7uF  [CAPC2013X135N]
C13  100nF  [CAPC1005X55N]
C14  100nF  [CAPC1005X55N]
C15  100nF  [CAPC1005X55N]
C16  100nF  [CAPC1005X55N]
C17  4.7uF  [CAPC2013X135N]
C18  1.0uF  [CAPC1005X55N]
C19  470pF  [CAPC1005X55N]
C20  22nF  [CAPC1608X90N]
C21  100nF  [CAPC1005X55N]
C32  1nF  [CAPC1005X55N]
C33  100nF  [CAPC1005X55N]
J6  RJ45  [XMultiple_XMG-9799-8821]
J7  DF14A-20P-1.25H(25)  [HIROSE_DF14A-20P-1.25H]
J8  SFW15S-2STE1LF  [FCI_SFW15S-2STE1LF]
J18  GBC05SBSN-M89  [SULLINS_GBC05SBSN-M89]
L1  220  [INDC2013X110N]
L2  DLP11SN900  [FIL_DLP11S]
L3  DLP11SN900  [FIL_DLP11S]
L4  DLP11SN900  [FIL_DLP11S]
L5  DLP11SN900  [FIL_DLP11S]
L6  DLP11SN900  [FIL_DLP11S]
L7  220  [INDC2013X110N]
Q1  2N7002T  [SOTFL50P160X80_GSD-3N]
R22  1.0K  [RESC1005X40N]
R23  1.0K  [RESC1005X40N]
R24  4.7K  [RESC1005X40N]
R25  4.7K  [RESC1005X40N]
R26  4.7K  [RESC1005X40N]
R27  4.7K  [RESC1005X40N]
R28  4.7K  [RESC1005X40N]
R29  4.7K  [RESC1005X40N]
R30  4.7K  [RESC1005X40N]
R31  4.7K  [RESC1005X40N]
R32  4.7K  [RESC1005X40N]
R33  4.7K  [RESC1005X40N]
R34  49.9  [RESC1005X40N]
R35  49.9  [RESC1005X40N]
R36  49.9  [RESC1005X40N]
R37  49.9  [RESC1005X40N]
R38  12.1k  [RESC1005X40N]
R39  0  [RESC1005X40N]
R40  150  [RESC1005X40N]
R41  150  [RESC1005X40N]
R42  0  [RESC3225X60N]
R43  10.0K  [RESC1005X40N]
R71  0  [RESC1609X55N]
R72  10.0K  [RESC1005X40N]
R73  100K  [RESC1005X40N]
R74  2.2K  [RESC1005X40N]
R75  2.2K  [RESC1005X40N]
U3  LAN8720Ai  [QFN50P400X400X100-25T260X260N]
U4  SI2323DS-T1-E3  [SOT95P240X110_GSD-3N]
U9  FXLP34P5X  [SOT65P210X110-5N]

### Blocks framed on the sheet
10/100M Ethernet: C9-C20 C32 J6 L1 Q1 R22-R42 R71-R73 U3 U4
LVDS: C33 J7 L2-L7 R43 U9
MIPI display: C21 J8 J18 R74 R75

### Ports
ENET0_CLK (bidir), ENET0_INT# (bidir), ENET0_MDC (bidir), ENET0_MDIO (bidir), ENET0_PWR (bidir), ENET0_RESET (bidir), ENET0_RX_CTL (bidir), ENET0_RX_ER (bidir), ENET0_RXD0 (bidir), ENET0_RXD1 (bidir), ENET0_TX_CTL (bidir), ENET0_TXD0 (bidir), ENET0_TXD1 (bidir), MIPI_DSI0_CLK_N (bidir), MIPI_DSI0_CLK_P (bidir), MIPI_DSI0_DATA0_N (bidir), MIPI_DSI0_DATA0_P (bidir), MIPI_DSI0_DATA1_N (bidir), MIPI_DSI0_DATA1_P (bidir), MIPI_DSI0_DATA2_N (bidir), MIPI_DSI0_DATA2_P (bidir), MIPI_DSI0_DATA3_N (bidir), MIPI_DSI0_DATA3_P (bidir), MIPI_DSI0_I2C0_SCL (bidir), MIPI_DSI0_I2C0_SDA (bidir), MIPI_DSI0_IRQ_N (bidir), MIPI_DSI0_PWM0_OUT (bidir)

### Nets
3V3_ETH0: C9.1 C32.2 L1.1 R22.1 R23.2 R24.2 R25.2 R26.1 R27.1 R28.1 R29.1 R71.2 U3.9(VDDIO) U4.D
3V3_EXT: C21.2 J7.1 J8.1 J8.2 R71.1 R72.2 R73.2 R74.2 R75.2 U4.S U9.5(VCC)
AVDD1: C10.2 C11.1 C12.2 J6.11 L1.2 R34.2 R35.2 R36.2 R37.2 R39.1 U3.1(VDD2A) U3.19(VDD1A)
GND: C9.2 C10.1 C11.2 C12.1 C13.2 C14.2 C15.2 C16.2 C17.1 C18.1 C19.1 C20.1 C21.1 C33.1 J7.4 J7.7 J7.10 J7.13 J8.3 J8.6 J8.9 J8.12 J8.15 J18.5 Q1.S R30.2 R31.2 R32.2 R33.2 R38.1 R40.2 R42.1 U3.25(GND_EP) U9.3(GND)
SHLD: J6.8(CHS_GROUND) J6.SHLD1 J6.SHLD2 R42.2
VDDCR1: C17.2 C18.2 C19.2 U3.6(VDDCR)
VIN: C33.2 J18.1 L7.1 R43.1 U9.1(VCC1)
ENET0_CLK: U3.5(XTAL1/CLKIN) ; port ENET0_CLK
ENET0_INT#: R25.1 U3.14(~{INT}/REFCLKO) ; port ENET0_INT#
ENET0_MDC: R23.1 U3.13(MDC) ; port ENET0_MDC
ENET0_MDIO: R22.2 U3.12(MDIO) ; port ENET0_MDIO
ENET0_PWR: Q1.G R73.1 ; port ENET0_PWR
ENET0_RESET: R24.1 U3.15(~{RST}) ; port ENET0_RESET
ENET0_RX_CTL: R27.2 R31.1 U3.11(CRS_DV/#MODE2) ; port ENET0_RX_CTL
ENET0_RX_ER: R26.2 R30.1 U3.10(RXER/#PHYAD0) ; port ENET0_RX_ER
ENET0_RXD0: R28.2 R32.1 U3.8(RXD0/#MODE0) ; port ENET0_RXD0
ENET0_RXD1: R29.2 R33.1 U3.7(RXD1/#MODE1) ; port ENET0_RXD1
ENET0_TX_CTL: U3.16(TXEN) ; port ENET0_TX_CTL
ENET0_TXD0: U3.17(TXD0) ; port ENET0_TXD0
ENET0_TXD1: U3.18(TXD1) ; port ENET0_TXD1
ETH0_LED1/#REGOFF: J6.9 U3.3(LED1/#REGOFF)
ETH0_LED2/#nINTSEL: R41.1 U3.2(LED2/#nINTSEL)
ETH0_RX_N: C16.1 J6.6(RD-) R37.1 U3.22(RXN)
ETH0_RX_P: C15.1 J6.3(RD+) R36.1 U3.23(RXP)
ETH0_TX_N: C14.1 J6.2(TD-) R35.1 U3.20(TXN)
ETH0_TX_P: C13.1 J6.1(TD+) R34.1 U3.21(TXP)
MIPI_DSI0_CLK_N: J8.11 L5.1 ; port MIPI_DSI0_CLK_N
MIPI_DSI0_CLK_P: J8.10 L5.4 ; port MIPI_DSI0_CLK_P
MIPI_DSI0_DATA0_N: J8.8 L2.1 ; port MIPI_DSI0_DATA0_N
MIPI_DSI0_DATA0_P: J8.7 L2.4 ; port MIPI_DSI0_DATA0_P
MIPI_DSI0_DATA1_N: J8.14 L3.1 ; port MIPI_DSI0_DATA1_N
MIPI_DSI0_DATA1_P: J8.13 L3.4 ; port MIPI_DSI0_DATA1_P
MIPI_DSI0_DATA2_N: L4.1 ; port MIPI_DSI0_DATA2_N
MIPI_DSI0_DATA2_P: L4.4 ; port MIPI_DSI0_DATA2_P
MIPI_DSI0_DATA3_N: L6.1 ; port MIPI_DSI0_DATA3_N
MIPI_DSI0_DATA3_P: L6.4 ; port MIPI_DSI0_DATA3_P
MIPI_DSI0_I2C0_SCL: J7.17 J8.5 J18.4 R74.1 ; port MIPI_DSI0_I2C0_SCL
MIPI_DSI0_I2C0_SDA: J7.18 J8.4 J18.3 R75.1 ; port MIPI_DSI0_I2C0_SDA
MIPI_DSI0_IRQ_N: J18.2 U9.4(Y) ; port MIPI_DSI0_IRQ_N
MIPI_DSI0_PWM0_OUT: J7.16 ; port MIPI_DSI0_PWM0_OUT
NetC20_2: C20.2 J6.4(CT) J6.5(CT) R39.2
NetC32_1: C32.1 Q1.D R72.1 U4.G
NetJ6_10: J6.10 R40.1
NetJ6_12: J6.12 R41.2
NetJ7_2: J7.2 L2.2
NetJ7_3: J7.3 L2.3
NetJ7_5: J7.5 L3.2
NetJ7_6: J7.6 L3.3
NetJ7_8: J7.8 L4.2
NetJ7_9: J7.9 L4.3
NetJ7_11: J7.11 L5.2
NetJ7_12: J7.12 L5.3
NetJ7_14: J7.14 L6.2
NetJ7_15: J7.15 L6.3
NetJ7_19: J7.19 R43.2 U9.2(A)
NetJ7_20: J7.20 L7.2
NetR38_2: R38.2 U3.24(RBIAS)

Not connected (* = marked no-connect by the designer): J6 7(NC)*; U3 4(XTAL2)*

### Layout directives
differential pair; net class DIFF100: ETH0_RX_N, ETH0_RX_P, ETH0_TX_N, ETH0_TX_P

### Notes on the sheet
- MODE[2:0]
- MODE DEFINITIONS
- 000
- 001
- 10Base-T Half Duplex. Auto-negotiation disabled
- 10Base-T Full Duplex. Auto-negotiation disabled
- (PHYAD[0])
- (MODE[0])
- (near R29) (MODE[1])
- (MODE[2])
- 010
- 011
- 100Base-TX Half Duplex. Auto-negotiation  disabled.
- 100Base-TX Full Duplex. Auto-negotiation disabled.
- 100
- 101
- 110
- 100Base-TX Half Duplex is advertised. Autonegotiation  enabled.
- Repeater mode. Auto-negotiation enabled
- Power Down mode.
- 111
- All capable. Auto-negotiation enabled.

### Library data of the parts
C9-C11 C13-C16 = 1000006: as C31 on sheet 02 - CC8X Module
C12 C17 = 1000500: CAP CER 4.7UF 25V 10% X5R 0805; Part_Type: Capacitor; Manufacturer: Murata; Manufacturer_Part_Number: GRM21BR61E475KA12L; Component_Life_Cycle_State: Reviewed; Area: 4.24; Project: SDR Prototype RF Board; Digi_PN: 14050307
C18 = 1001167: CAP CER 1UF 10V 10% X5R 0402; Part_Type: Capacitor; Manufacturer: Murata; Manufacturer_Part_Number: GRM155R61A105KE15D; Digi_PN: 14050399; Component_Life_Cycle_State: Reviewed; Area: 0.95; Project: CCWMX6_SBC board
C19 = 1001576: CAP CER 470PF 50V 5% NP0 0402; Part_Type: Capacitor; Manufacturer: Murata; Manufacturer_Part_Number: GRM1555C1H471JA01J; Digi_PN: 14050366; Component_Life_Cycle_State: Reviewed; Area: 0,95; Project: WDNU-II; Tolerance: +/- 5%
C20 = 1001024: CAP CER 0.022UF 100V X7R 0603; Part_Type: Capacitor; Manufacturer: TDK Corporation; Manufacturer_Part_Number: C1608X7R2A223M080AA; Digi_PN: 14050726; Component_Life_Cycle_State: Reviewed; Area: 2,27; Project: ResMed RF Test Interface Board
C21 C33 = 1000006: CAP 100nF 16V 10% X7R 0402; Part_Type: Capacitor; Manufacturer: Murata; Manufacturer_Part_Number: GRM155R71C104KA88D; Digi_PN: 14050552; Component_Life_Cycle_State: CAD Reviewed; Area: 0,95; Project: KITT; Tolerance: 10
C32 = 1000067: CAP CER 1000PF 50V 10% X7R 0402; Part_Type: Capacitor; Manufacturer: Murata; Manufacturer_Part_Number: GRM155R71H102KA01D; Digi_PN: 14050737; Component_Life_Cycle_State: Proven; Area: 0,95; Project: Adjustable Foundation
J6 = 1001971: CONN, RJ45 100BASE-T R/A, -40/85C; Part_Type: Connector; Manufacturer: XMultiple; Manufacturer_Part_Number: XMG-9799-8821-100D-L1TO-H-HIM; Digi_PN: 18000733; Component_Life_Cycle_State: Reviewed; Area: 337; Project: iMX6UL+PMIC
J7 = 1001132: CONN HEADER 20POS 1.25MM R/A SMD; Part_Type: Connector; Manufacturer: Hirose; Digi_PN: 18050231; Component_Life_Cycle_State: Reviewed; Area: 206,34; Project: CCWMX6_SBC board
J8 = 1001866: CONN FFC FPC VERT 15POS 1MM SMD; Part_Type: Connector; Manufacturer: FCI; Digi_PN: 18000730; Component_Life_Cycle_State: Reviewed; Area: 128,76; Project: CCiMX6 SBC MFG TEST BOARD
J18 = 1002541: CONN HEADER 5POS .100 RT/A SMD; Part_Type: Connector; Manufacturer: Sullins; Digi_PN: 18050380; Component_Life_Cycle_State: Created; Area: 184,19; Project: DIGI CC8X SOM
L1 = 1001174: FERRITE BEAD 220 OHM 2.0A 0805; Manufacturer: Wurth Electronics Inc; Manufacturer_Part_Number: 742792022; Digi_PN: 21000146; Component_Life_Cycle_State: Reviewed; Area: 4.24; Project: CCWMX6_SBC board
L2-L6 = 1001014: CHOKE COIL COMMON MODE 150MA SMD; Part_Type: Inductor; Manufacturer: Murata; Manufacturer_Part_Number: DLP11SN900HL2L; Digi_PN: 21000531; Component_Life_Cycle_State: Reviewed; Area: 3,94; Project: ResMed RF Test Interface Board
L7 = 1001174: FERRITE BEAD 220 OHM 2.0A 0805; Manufacturer: Wurth Electronics Inc; Manufacturer_Part_Number: 742792022; Digi_PN: 21000146; Component_Life_Cycle_State: Reviewed; Area: 4,24; Project: CCWMX6_SBC board
Q1 = 1000715: MOSFET N-CH 60V 115MA SOT-523F; Part_Type: Transistor; Manufacturer: Fairchild Semiconductor; Note: 17050841 = Digi No. for GE WDNU; Digi_PN: 17050797; Component_Life_Cycle_State: CAD Reviewed; Area: 3,06; Project: SmartMeter2
R22 = 1000079: RES 1.00K OHM 1/10W 1% 0402 SMD; Part_Type: Resistor; Manufacturer: Panasonic - ECG; Manufacturer_Part_Number: ERJ-2RKF1001X; Digi_PN: 13051085; Component_Life_Cycle_State: Proven; Area: 0.95; Project: Adjustable Foundation; Power_WV_SRF: 10
R23 R39 = 1000076: as R9 on sheet 03 - Power, boot mode, reset, console, microSD, SWD, Coin Cell
R24-R33 = 1000038: RES 4.7K OHM 1/10W 5% 0402 SMD; Part_Type: Resistor; Manufacturer: Panasonic - ECG; Manufacturer_Part_Number: ERJ-2GEJ472X; Component_Life_Cycle_State: Proven; Area: 0.95; Project: Adjustable Foundation; Power_WV_SRF: 100; Tolerance: 5; Digi_PN: 13050549
R34-R37 = 1000466: RES 49.9 OHM 1/10W 1% 0402 SMD; Part_Type: Resistor; Manufacturer: Panasonic - ECG; Manufacturer_Part_Number: ERJ-2RKF49R9X; Digi_PN: 13051083; Component_Life_Cycle_State: CAD Reviewed; Area: 0,95; Project: KITT; Power_WV_SRF: 100
R38 = 1000828: RES 12.1K OHM 1/10W 1% 0402 SMD; Part_Type: Resistor; Manufacturer: Panasonic - ECG; Manufacturer_Part_Number: ERJ-2RKF1212X; Component_Life_Cycle_State: Reviewed; Area: 0.95; Project: SmartMeter2; Power_WV_SRF: 100; Digi_PN: 13051088
R40 R41 = 1000465: RES 150 OHM 1/10W 1% 0402 SMD; Part_Type: Resistor; Manufacturer: Panasonic - ECG; Manufacturer_Part_Number: ERJ-2RKF1500X; Digi_PN: 13050557; Component_Life_Cycle_State: CAD Reviewed; Area: 0.95; Project: KITT; Power_WV_SRF: 100
R42 = 1000229: RES 0.0 OHM 1/2W 1210 SMD; Part_Type: Resistor; Manufacturer: Vishay Dale; Manufacturer_Part_Number: CRCW12100000Z0EA; Digi_PN: 13050962; Component_Life_Cycle_State: Proven; Area: 11,07; Project: Adjustable Foundation
R43 R72 = 1000537: RES 10.0K OHM 1/10W 1% 0402 SMD; Part_Type: Resistor; Manufacturer: Panasonic - ECG; Manufacturer_Part_Number: ERJ-2RKF1002X; Digi_PN: 13051084; Component_Life_Cycle_State: CAD Reviewed; Area: 0,95; Project: KITT; Power_WV_SRF: 100
R71 = 1000208: RES 0.0 OHM 1/10W 0603; Part_Type: Resistor; Manufacturer: Panasonic - ECG; Manufacturer_Part_Number: ERJ-3GEY0R00V; Note: 13051103 = Digi No. for GE WDNU; Digi_PN: 13050568; Component_Life_Cycle_State: Reviewed; Area: 2,5; Project: Adjustable Foundation; Voltage: 75V
R73 = 1000480: as R11 on sheet 03 - Power, boot mode, reset, console, microSD, SWD, Coin Cell
R74 R75 = 1001156: RES 2.20K OHM 1/16W 1% 0402 SMD; Part_Type: Resistor; Manufacturer: Yageo; Manufacturer_Part_Number: RC0402FR-072K2L; Note: 13051099 = Digi No. for GE WDNU; Digi_PN: 13050699; Component_Life_Cycle_State: Reviewed; Area: 0,95; Project: CCWMX6_SBC board
U3 = 1001970: TXRX ETHERNET 10/100 24VQFN; Part_Type: IC; Manufacturer: Micrel; Manufacturer_Part_Number: LAN8720Ai-CP-TR; Digi_PN: 16052022; Component_Life_Cycle_State: Created; Area: 27,46; Project: iMX6UL+PMIC
U4 = 1001163: MOSFET P-CH 20V 3.7A SOT23-3; Part_Type: IC; Manufacturer: Vishay Siliconix; Digi_PN: 17050358; Component_Life_Cycle_State: Reviewed; Area: 10,92; Project: CCWMX6_SBC board
U9 = 1000759: TRANSLATOR 1BIT UNIDIRECT SC70-; Part_Type: IC; Manufacturer: Fairchild Semiconductor; Digi_PN: 16051662; Component_Life_Cycle_State: Reviewed; Area: 6.93; Project: CLC

## Sheet 05 - USB Host-Device, Raspberry PI expansion, User LED and button, XBee.SchDoc: MicroSD, USB Host/Device, Console
size A3; PageSetup: Record=PageOptions¦CenterHorizontal=True¦CenterVertical=True¦PrintScale=0.71¦XCorrection=1.00¦YCorrection=1.00¦PrintKind=0¦BorderSize=5000000¦LeftOffset=0¦BottomOffset=0¦Orientation=2¦PaperLength=4200¦PaperWidth=2970¦Scale=100¦PaperSource=7¦PrintQuality=600¦MediaType=1¦DitherType=10¦PrintScaleMode=1¦PaperKind=A4; Author: Juan Anzola; SheetNumber: 5; SheetTotal: 7
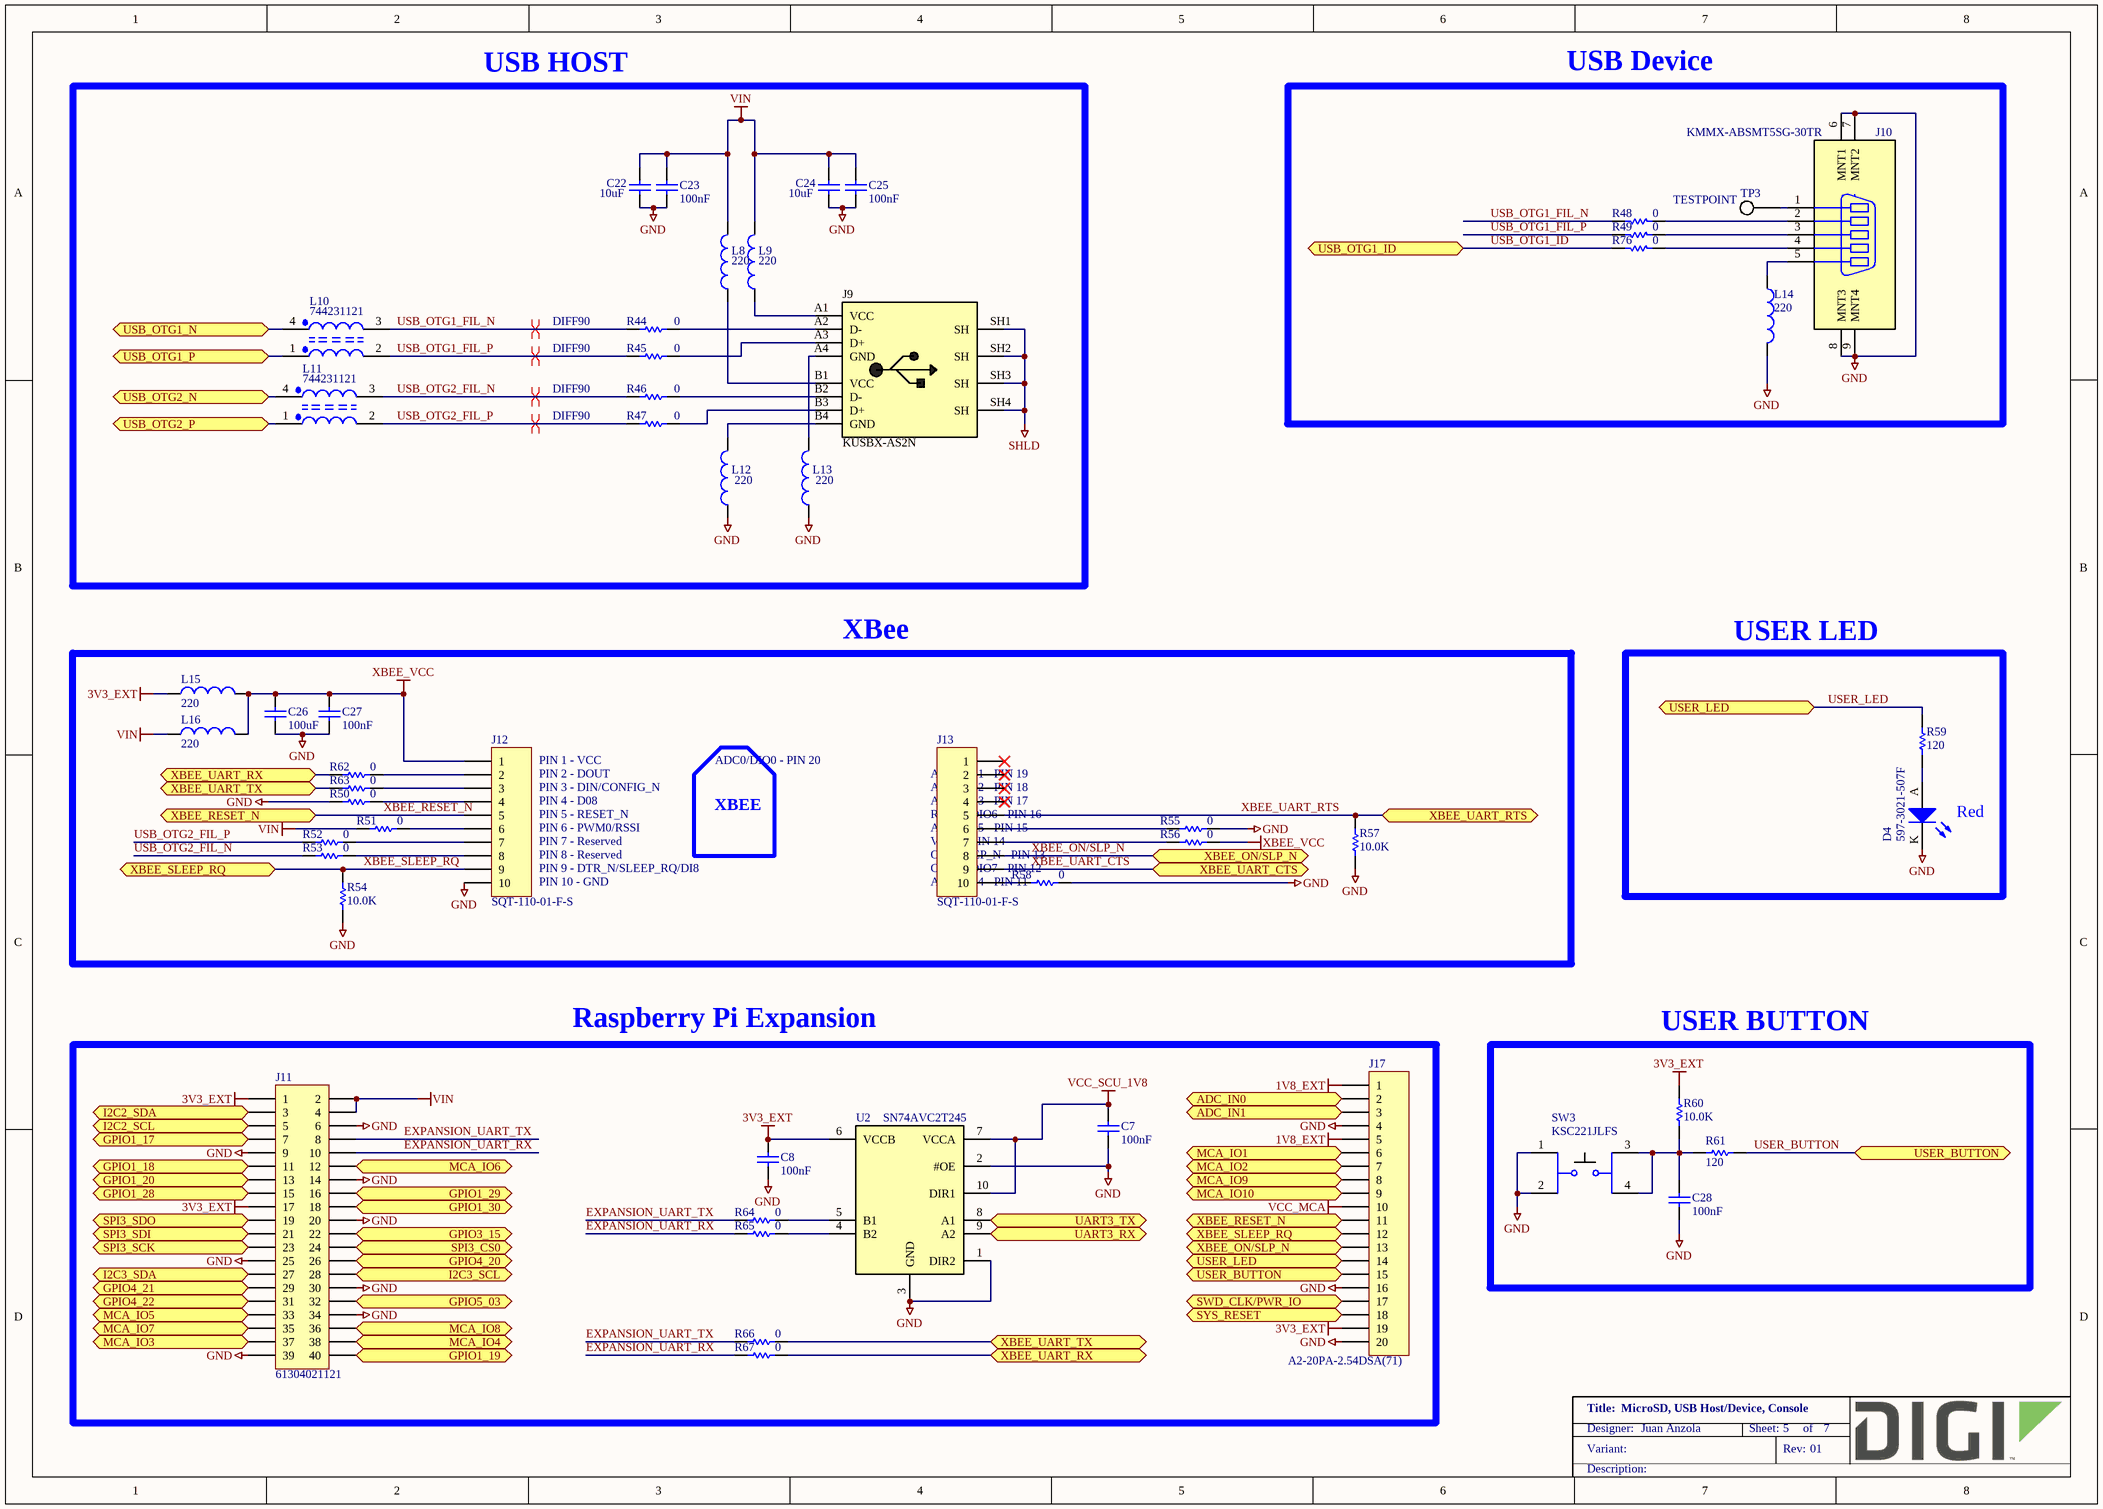
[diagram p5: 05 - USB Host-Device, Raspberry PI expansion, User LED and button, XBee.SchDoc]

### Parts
C7  100nF  [CAPC1005X55N]
C8  100nF  [CAPC1005X55N]
C22  10uF  [CAPC1005X55N]
C23  100nF  [CAPC1005X55N]
C24  10uF  [CAPC1005X55N]
C25  100nF  [CAPC1005X55N]
C26  100uF  [CAPC3216X190N]
C27  100nF  [CAPC1005X55N]
C28  100nF  [CAPC1005X55N]
D4  597-3021-507F  [LEDM3020X130N]
J9  KUSBX-AS2N  [KYCON_KUSBX-AS2N]
J10  KMMX-ABSMT5SG-30TR  [KYCON_KMMX-ABSMT5]
J11  61304021121  [Wurth_61304021121]
J12  SQT-110-01-F-S  [SAMTEC_SQT-110-01-F-S]
J13  SQT-110-01-F-S  [SAMTEC_SQT-110-01-F-S]
J17  A2-20PA-2.54DSA(71)  [HIROSE_A2-20PA-2.54DSA(71)]
L8  220  [INDC2013X110N]
L9  220  [INDC2013X110N]
L10  744231121  [FIL_DLW21H]
L11  744231121  [FIL_DLW21H]
L12  220  [INDC2013X110N]
L13  220  [INDC2013X110N]
L14  220  [INDC2013X110N]
L15  220  [INDC2013X110N]
L16  220  [INDC2013X110N]
R44  0  [RESC1005X40N]
R45  0  [RESC1005X40N]
R46  0  [RESC1005X40N]
R47  0  [RESC1005X40N]
R48  0  [RESC1005X40N]
R49  0  [RESC1005X40N]
R50  0  [RESC1005X40N]
R51  0  [RESC1005X40N]
R52  0  [RESC1005X40N]
R53  0  [RESC1005X40N]
R54  10.0K  [RESC1005X40N]
R55  0  [RESC1005X40N]
R56  0  [RESC1005X40N]
R57  10.0K  [RESC1005X40N]
R58  0  [RESC1005X40N]
R59  120  [RESC1005X40N]
R60  10.0K  [RESC1005X40N]
R61  120  [RESC1005X40N]
R62  0  [RESC1005X40N]
R63  0  [RESC1005X40N]
R64  0  [RESC1005X40N]
R65  0  [RESC1005X40N]
R66  0  [RESC1005X40N]
R67  0  [RESC1005X40N]
R76  0  [RESC1005X40N]
SW3  KSC221JLFS  [SW_KSC221J]
TP3  TESTPOINT  [TP0762]  (no BOM)
U2  SN74AVC2T245  [QFN40P260X180X55-16N]

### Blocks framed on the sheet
USB HOST: C22-C25 J9 L8-L13 R44-R47
USB Device: J10 L14 R48 R49 R76 TP3
XBee: C26 C27 J12 J13 L15 L16 R50-R58 R62 R63
USER LED: D4 R59
Raspberry Pi Expansion: C7 C8 J11 J17 R64-R67 U2
USER BUTTON: C28 R60 R61 SW3

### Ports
ADC_IN0 (bidir), ADC_IN1 (bidir), GPIO1_17 (bidir), GPIO1_18 (bidir), GPIO1_19 (bidir), GPIO1_20 (bidir), GPIO1_28 (bidir), GPIO1_29 (bidir), GPIO1_30 (bidir), GPIO3_15 (bidir), GPIO4_20 (bidir), GPIO4_21 (bidir), GPIO4_22 (bidir), GPIO5_03 (bidir), I2C2_SCL (bidir), I2C2_SDA (bidir), I2C3_SCL (bidir), I2C3_SDA (bidir), MCA_IO1 (bidir), MCA_IO2 (bidir), MCA_IO3 (bidir), MCA_IO4 (bidir), MCA_IO5 (bidir), MCA_IO6 (bidir), MCA_IO7 (bidir), MCA_IO8 (bidir), MCA_IO9 (bidir), MCA_IO10 (bidir), SPI3_CS0 (bidir), SPI3_SCK (bidir), SPI3_SDI (bidir), SPI3_SDO (bidir), SWD_CLK/PWR_IO (bidir), SYS_RESET (bidir), UART3_RX (bidir), UART3_TX (bidir), USB_OTG1_ID (bidir), USB_OTG1_N (bidir), USB_OTG1_P (bidir), USB_OTG2_N (bidir), USB_OTG2_P (bidir), USER_BUTTON (bidir), USER_LED (bidir), XBEE_ON/SLP_N (bidir), XBEE_RESET_N (bidir), XBEE_SLEEP_RQ (bidir), XBEE_UART_CTS (bidir), XBEE_UART_RTS (bidir), XBEE_UART_RX (bidir), XBEE_UART_TX (bidir)

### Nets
1V8_EXT: J17.1 J17.5
3V3_EXT: C8.2 J11.1 J11.17 J17.19 L15.1 R60.2 U2.6(VCCB)
GND: C7.1 C8.1 C22.1 C23.1 C24.1 C25.1 C26.2 C27.1 C28.1 D4.K J10.6(MNT1) J10.7(MNT2) J10.8(MNT3) J10.9(MNT4) J11.6 J11.9 J11.14 J11.20 J11.25 J11.30 J11.34 J11.39 J12.10 J17.4 J17.16 J17.20 L12.1 L13.1 L14.1 R50.1 R54.1 R55.2 R57.1 R58.2 SW3.1 SW3.2 U2.1(DIR2) U2.2(#OE) U2.3(GND)
SHLD: J9.SH1(SH) J9.SH2(SH) J9.SH3(SH) J9.SH4(SH)
VCC_MCA: J17.10
VCC_SCU_1V8: C7.2 U2.7(VCCA) U2.10(DIR1)
VIN: C22.2 C23.2 C24.2 C25.2 J11.2 J11.4 L8.2 L9.2 L16.1 R51.1
XBEE_VCC: C26.1 C27.2 J12.1 L15.2 L16.2 R56.2
ADC_IN0: J17.2 ; port ADC_IN0
ADC_IN1: J17.3 ; port ADC_IN1
EXPANSION_UART_RX: J11.10 R65.1 R67.1
EXPANSION_UART_TX: J11.8 R64.1 R66.1
GPIO1_17: J11.7 ; port GPIO1_17
GPIO1_18: J11.11 ; port GPIO1_18
GPIO1_19: J11.40 ; port GPIO1_19
GPIO1_20: J11.13 ; port GPIO1_20
GPIO1_28: J11.15 ; port GPIO1_28
GPIO1_29: J11.16 ; port GPIO1_29
GPIO1_30: J11.18 ; port GPIO1_30
GPIO3_15: J11.22 ; port GPIO3_15
GPIO4_20: J11.26 ; port GPIO4_20
GPIO4_21: J11.29 ; port GPIO4_21
GPIO4_22: J11.31 ; port GPIO4_22
GPIO5_03: J11.32 ; port GPIO5_03
I2C2_SCL: J11.5 ; port I2C2_SCL
I2C2_SDA: J11.3 ; port I2C2_SDA
I2C3_SCL: J11.28 ; port I2C3_SCL
I2C3_SDA: J11.27 ; port I2C3_SDA
MCA_IO1: J17.6 ; port MCA_IO1
MCA_IO2: J17.7 ; port MCA_IO2
MCA_IO3: J11.37 ; port MCA_IO3
MCA_IO4: J11.38 ; port MCA_IO4
MCA_IO5: J11.33 ; port MCA_IO5
MCA_IO6: J11.12 ; port MCA_IO6
MCA_IO7: J11.35 ; port MCA_IO7
MCA_IO8: J11.36 ; port MCA_IO8
MCA_IO9: J17.8 ; port MCA_IO9
MCA_IO10: J17.9 ; port MCA_IO10
SPI3_CS0: J11.24 ; port SPI3_CS0
SPI3_SCK: J11.23 ; port SPI3_SCK
SPI3_SDI: J11.21 ; port SPI3_SDI
SPI3_SDO: J11.19 ; port SPI3_SDO
SWD_CLK/PWR_IO: J17.17 ; port SWD_CLK/PWR_IO
SYS_RESET: J17.18 ; port SYS_RESET
UART3_RX: U2.9(A2) ; port UART3_RX
UART3_TX: U2.8(A1) ; port UART3_TX
USB_OTG1_FIL_N: L10.3 R44.1 R48.2
USB_OTG1_FIL_P: L10.2 R45.1 R49.2
USB_OTG1_ID: R76.2 ; port USB_OTG1_ID
USB_OTG1_N: L10.4 ; port USB_OTG1_N
USB_OTG1_P: L10.1 ; port USB_OTG1_P
USB_OTG2_FIL_N: L11.3 R46.1 R53.1
USB_OTG2_FIL_P: L11.2 R47.1 R52.1
USB_OTG2_N: L11.4 ; port USB_OTG2_N
USB_OTG2_P: L11.1 ; port USB_OTG2_P
USER_BUTTON: J17.15 R61.1 ; port USER_BUTTON
USER_LED: J17.14 R59.2 ; port USER_LED
XBEE_ON/SLP_N: J13.8 J17.13 ; port XBEE_ON/SLP_N
XBEE_RESET_N: J12.5 J17.11 ; port XBEE_RESET_N
XBEE_SLEEP_RQ: J12.9 J17.12 R54.2 ; port XBEE_SLEEP_RQ
XBEE_UART_CTS: J13.9 ; port XBEE_UART_CTS
XBEE_UART_RTS: J13.5 R57.2 ; port XBEE_UART_RTS
XBEE_UART_RX: R62.1 R67.2 ; port XBEE_UART_RX
XBEE_UART_TX: R63.1 R66.2 ; port XBEE_UART_TX
NetC28_2: C28.2 R60.1 R61.2 SW3.3 SW3.4
NetD4_A: D4.A R59.1
NetJ9_A1: J9.A1(VCC) L9.1
NetJ9_A2: J9.A2(D-) R44.2
NetJ9_A3: J9.A3(D+) R45.2
NetJ9_A4: J9.A4(GND) L13.2
NetJ9_B1: J9.B1(VCC) L8.1
NetJ9_B2: J9.B2(D-) R46.2
NetJ9_B3: J9.B3(D+) R47.2
NetJ9_B4: J9.B4(GND) L12.2
NetJ10_1: J10.1 TP3.1
NetJ10_2: J10.2 R48.1
NetJ10_3: J10.3 R49.1
NetJ10_4: J10.4 R76.1
NetJ10_5: J10.5 L14.2
NetJ12_2: J12.2 R62.2
NetJ12_3: J12.3 R63.2
NetJ12_4: J12.4 R50.2
NetJ12_6: J12.6 R51.2
NetJ12_7: J12.7 R52.2
NetJ12_8: J12.8 R53.2
NetJ13_6: J13.6 R55.1
NetJ13_7: J13.7 R56.1
NetJ13_10: J13.10 R58.1
NetR64_2: R64.2 U2.5(B1)
NetR65_2: R65.2 U2.4(B2)

Not connected (* = marked no-connect by the designer): J13 1* 2* 3* 4*

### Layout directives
differential pair; net class DIFF90: USB_OTG1_FIL_N, USB_OTG1_FIL_P, USB_OTG2_FIL_N, USB_OTG2_FIL_P

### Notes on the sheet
- (near J12) PIN 1 - VCC
- (near J12) PIN 2 - DOUT
- (near J13) ADC0/DIO0 - PIN 20
- (near J13) AD1/DIO1 - PIN 19
- (near J12) PIN 3 - DIN/CONFIG_N
- (near J12) PIN 4 - D08
- (near J12) PIN 5 - RESET_N
- (near J12) PIN 6 - PWM0/RSSI
- (near J12) PIN 7 - Reserved
- (near J12) PIN 8 - Reserved
- XBEE
- (near J13) ON/SLEEP_N - PIN 13
- (near J13) VREF - PIN 14
- (near J13) AD5/DIO5 - PIN 15
- (near J13) AD3/DIO3 - PIN 17
- (near J13) AD2/DIO2 - PIN 18
- (near J13) RTS_N/DIO6 - PIN 16
- (near D4) Red
- (near J12) PIN 9 - DTR_N/SLEEP_RQ/DI8
- (near J12) PIN 10 - GND
- (near J13) AD4/DIO4 - PIN 11
- (near J13) CTS_N/DIO7 - PIN 12

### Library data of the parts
C7 C8 C27 = 1000006: as C21 on sheet 04 - 10-100 Mb Ethernet, LVDS, MIPI
C22 C24 = 1001168: as C5 on sheet 03 - Power, boot mode, reset, console, microSD, SWD, Coin Cell
C23 C25 C28 = 1000006: as C31 on sheet 02 - CC8X Module
C26 = 1000566: CAP CER 100UF 10V 20% X5R 1206; Part_Type: Capacitor; Manufacturer: TDK Corporation; Manufacturer_Part_Number: C3216X5R1A107M; Digi_PN: 14050666; Component_Life_Cycle_State: Reviewed; Area: 7,47; Project: GSM Cell PCB
D4 = 1001190: LED RED 653NM 20MA 1208 SMD; Manufacturer: Dialight; Digi_PN: 17050184; Component_Life_Cycle_State: Reviewed; Area: 6; Project: CCWMX6_SBC board
J9 = 1001121: USB Stacked Dual A type; Part_Type: Connector; Manufacturer: KYCON; Digi_PN: 18000276; Component_Life_Cycle_State: Reviewed; Area: 164; Project: CCWMX6_SBC board
J10 = 1001117: CONN RECEPT MICRO-USB TYPE AB R/A; Part_Type: Connector; Manufacturer: KYCON; Digi_PN: 18000401; Component_Life_Cycle_State: Reviewed; Area: 40; Project: CCWMX6_SBC board
J11 = 1002007: CONN HEADER VERT 40POS 2.54; Part_Type: Connector; Manufacturer: Wurth Electronics Inc; Digi_PN: 00480040; Component_Life_Cycle_State: Created; Area: 250; Project: iMX6UL+PMIC
J12 J13 = 1001648: CONN RECEPT 10POS 10X1 2MM PCB TH; Part_Type: Connector; Manufacturer: Samtec; Component_Life_Cycle_State: Reviewed; Area: 53.17; Project: CareTaker IV; Digi_PN: 18050108
J17 = 1002537: HEADER 20POS 2.54MM; Part_Type: Connector; Manufacturer: Hirose; Digi_PN: 18000761; Component_Life_Cycle_State: Created; Area: 179,38; Project: DIGI CC8X SOM
L8 L9 L12-L14 = 1001174: as L1 on sheet 04 - 10-100 Mb Ethernet, LVDS, MIPI
L10 L11 = 1001173: CHOKE COM MODE 120 OHM .37A; Part_Type: Inductor; Manufacturer: Wurth Electronics Inc; Digi_PN: 21000143; Component_Life_Cycle_State: Reviewed; Area: 2.4; Project: CCWMX6_SBC board
L15 L16 = 1001174: as L7 on sheet 04 - 10-100 Mb Ethernet, LVDS, MIPI
R44-R53 R55 R56 R58 R62-R67 R76 = 1000076: as R3 on sheet 02 - CC8X Module
R54 R57 = 1000537: as R43 on sheet 04 - 10-100 Mb Ethernet, LVDS, MIPI
R59 R61 = 1001158: as R68 on sheet 03 - Power, boot mode, reset, console, microSD, SWD, Coin Cell
R60 = 1000537: as R4 on sheet 03 - Power, boot mode, reset, console, microSD, SWD, Coin Cell
SW3 = 1001124: as SW1 on sheet 03 - Power, boot mode, reset, console, microSD, SWD, Coin Cell
TP3 = CAD0011: TEST POINT 30mil PAD SMT; Component_Life_Cycle_State: Reviewed; Area: 0.58; Project: CLC
U2 = 1002531: IC BUS TRANSCVR TRI-ST DL 10UQFN; Manufacturer: Texas Instruments; Manufacturer_Part_Number: SN74AVC2T245RSWR; Digi_PN: 16052024; Component_Life_Cycle_State: Created; Area: 11,67; Project: DIGI CC8X SOM

## Sheet 06 - GPIO Table, System Power rails.SchDoc: GPIO Table, System Power Rails
size A3; PageSetup: Record=PageOptions¦CenterHorizontal=True¦CenterVertical=True¦PrintScale=1.01¦XCorrection=1.00¦YCorrection=1.00¦PrintKind=0¦BorderSize=5000000¦LeftOffset=0¦BottomOffset=0¦Orientation=2¦PaperLength=4200¦PaperWidth=2970¦Scale=100¦PaperSource=15¦PrintQuality=600¦MediaType=1¦DitherType=10¦PrintScaleMode=1¦PaperKind=A3¦PaperIndex=8; Author: Juan Anzola; SheetNumber: 6; SheetTotal: 7
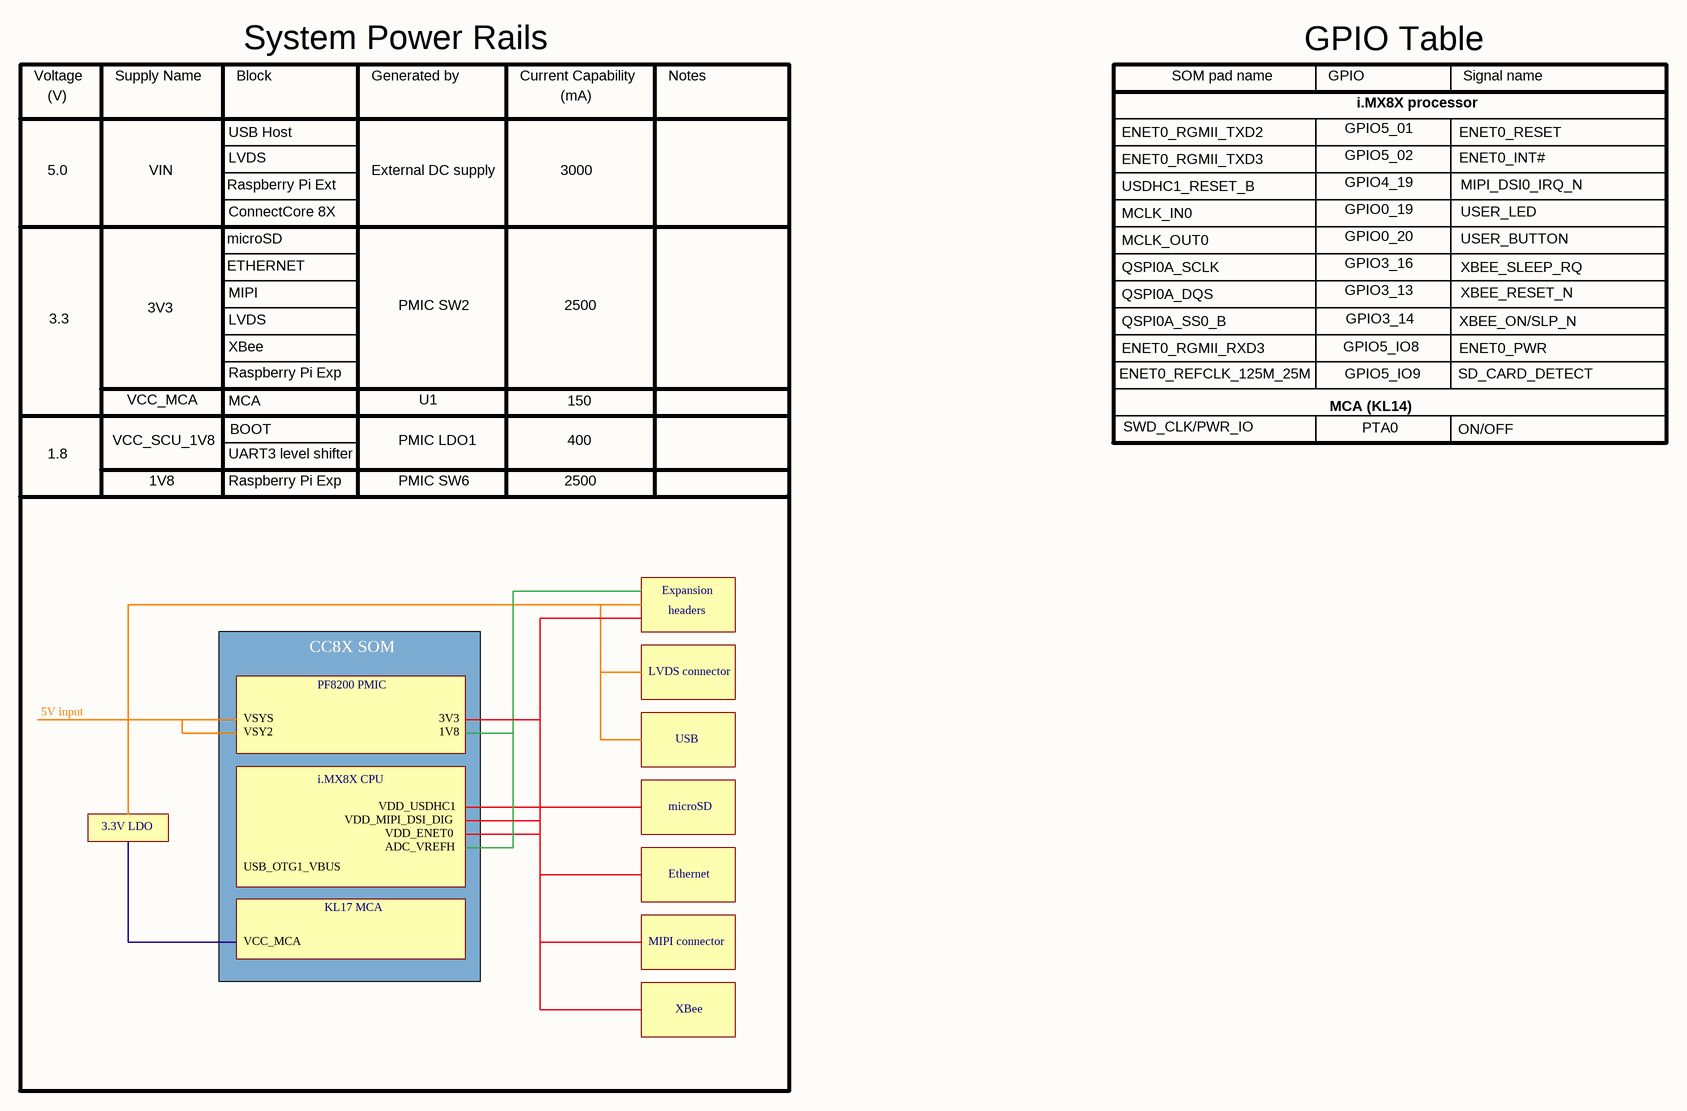
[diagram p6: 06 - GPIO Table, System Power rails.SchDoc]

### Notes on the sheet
- Voltage
- (V)
- Supply Name
- Block
- System Power Rails
- Generated by
- Current Capability
- (mA)
- Notes
- SOM pad name
- GPIO Table
- GPIO
- i.MX8X processor
- Signal name
- 5.0
- VIN
- USB Host
- LVDS
- External DC supply
- 3000
- ENET0_RGMII_TXD2
- ENET0_RGMII_TXD3
- GPIO5_01
- GPIO5_02
- GPIO4_19
- ENET0_RESET
- ENET0_INT#
- microSD
- Raspberry Pi Ext
- ConnectCore 8X
- USDHC1_RESET_B
- MCLK_IN0
- MCLK_OUT0
- GPIO0_19
- GPIO0_20
- MIPI_DSI0_IRQ_N
- USER_LED
- USER_BUTTON
- 3V3
- ETHERNET
- MIPI
- PMIC SW2
- 2500
- QSPI0A_SCLK
- QSPI0A_DQS
- GPIO3_16
- GPIO3_13
- XBEE_SLEEP_RQ
- XBEE_RESET_N
- 3.3
- Raspberry Pi Exp
- XBee
- ENET0_REFCLK_125M_25M
- QSPI0A_SS0_B
- ENET0_RGMII_RXD3
- GPIO5_IO8
- GPIO5_IO9
- GPIO3_14
- SD_CARD_DETECT
- XBEE_ON/SLP_N
- ENET0_PWR
- VCC_SCU_1V8
- VCC_MCA
- MCA
- BOOT
- PMIC LDO1
- U1
- 150
- 400
- SWD_CLK/PWR_IO
- MCA (KL14)
- PTA0
- ON/OFF
- 1.8
- 1V8
- UART3 level shifter
- PMIC SW6
- CC8X SOM
- Expansion
- headers
- 5V input
- VSYS
- PF8200 PMIC
- LVDS connector
- VSY2
- i.MX8X CPU
- USB
- 3.3V LDO
- VDD_MIPI_DSI_DIG
- VDD_USDHC1
- VDD_ENET0
- ADC_VREFH
- USB_OTG1_VBUS
- KL17 MCA
- Ethernet
- MIPI connector

## Sheet 07 - History, Mechanicals.SchDoc: History
size A3; PageSetup: Record=PageOptions¦CenterHorizontal=True¦CenterVertical=True¦PrintScale=1.01¦XCorrection=1.00¦YCorrection=1.00¦PrintKind=0¦BorderSize=5000000¦LeftOffset=0¦BottomOffset=0¦Orientation=2¦PaperLength=4200¦PaperWidth=2970¦Scale=100¦PaperSource=15¦PrintQuality=600¦MediaType=1¦DitherType=10¦PrintScaleMode=1¦PaperKind=A3¦PaperIndex=8; Author: Juan Anzola; SheetNumber: 7; SheetTotal: 7
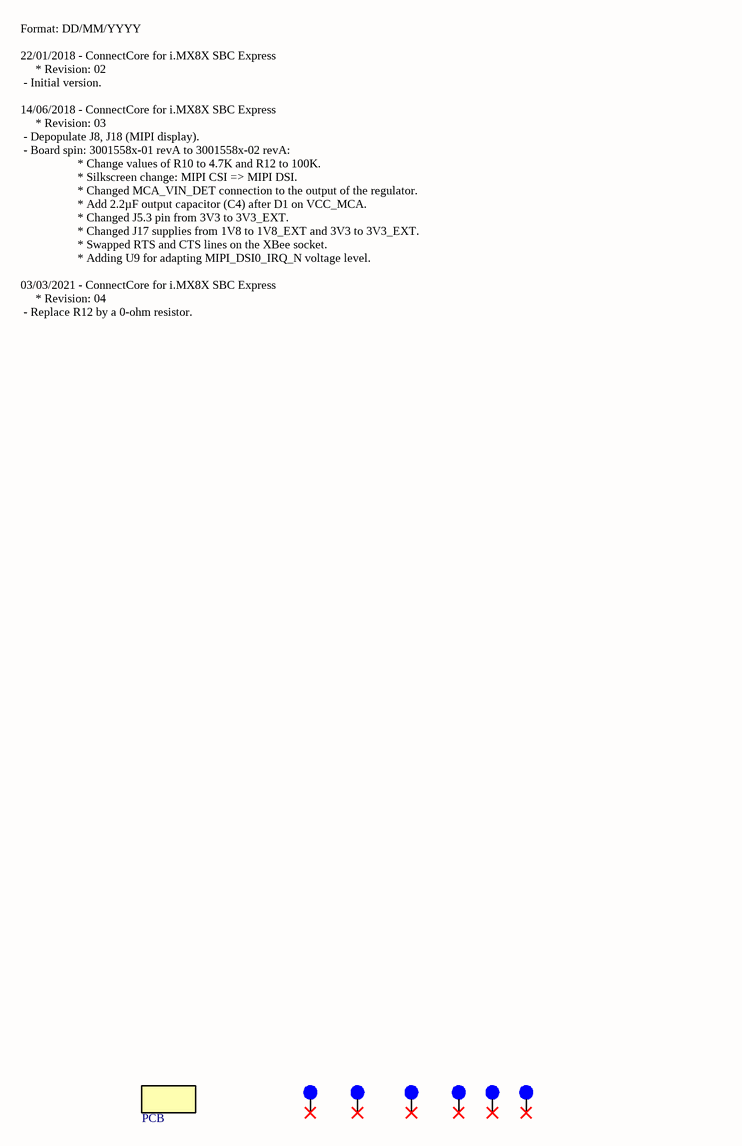
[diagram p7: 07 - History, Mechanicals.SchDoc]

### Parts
FIDUCIAL1  40mil FID  [fiducial_40mil_round]  (value not drawn)  (no BOM)
FIDUCIAL2  40mil FID  [fiducial_40mil_round]  (value not drawn)  (no BOM)
FIDUCIAL3  40mil FID  [fiducial_40mil_round]  (value not drawn)  (no BOM)
FIDUCIAL7  40mil FID  [fiducial_40mil_round]  (value not drawn)  (no BOM)
FIDUCIAL8  40mil FID  [fiducial_40mil_round]  (value not drawn)  (no BOM)
FIDUCIAL9  40mil FID  [fiducial_40mil_round]  (value not drawn)  (no BOM)
PCB1  PCB  [PCBNUMBER]

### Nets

Not connected (* = marked no-connect by the designer): FIDUCIAL1 1(Fid_1)*; FIDUCIAL2 1(Fid_1)*; FIDUCIAL3 1(Fid_1)*; FIDUCIAL7 1(Fid_1)*; FIDUCIAL8 1(Fid_1)*; FIDUCIAL9 1(Fid_1)*

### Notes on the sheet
- Format: DD/MM/YYYY
  22/01/2018 - ConnectCore for i.MX8X SBC Express
  * Revision: 02
  - Initial version.
  14/06/2018 - ConnectCore for i.MX8X SBC Express
  * Revision: 03
  - Depopulate J8, J18 (MIPI display).
  - Board spin: 3001558x-01 revA to 3001558x-02 revA:
  * Change values of R10 to 4.7K and R12 to 100K.
  * Silkscreen change: MIPI CSI => MIPI DSI.
  * Changed MCA_VIN_DET connection to the output of the regulator.
  * Add 2.2µF output capacitor (C4) after D1 on VCC_MCA.
  * Changed J5.3 pin from 3V3 to 3V3_EXT.
  * Changed J17 supplies from 1V8 to 1V8_EXT and 3V3 to 3V3_EXT.
  * Swapped RTS and CTS lines on the XBee socket.
  * Adding U9 for adapting MIPI_DSI0_IRQ_N voltage level.
  03/03/2021 - ConnectCore for i.MX8X SBC Express
  * Revision: 04
  - Replace R12 by a 0-ohm resistor.

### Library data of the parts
FIDUCIAL1-FIDUCIAL3 FIDUCIAL7-FIDUCIAL9 = CAD0023: 40 Mil Round Fiducial; Part_Type: Mechanical; Component_Life_Cycle_State: Reviewed; Area: 1; Project: SDR Prototype RF Board
PCB1 = 3000137: PCB CCWM6_SBC_v0.3; Digi_PN: 30014752-02; Component_Life_Cycle_State: Created; Project: CCWMX6_SBC board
